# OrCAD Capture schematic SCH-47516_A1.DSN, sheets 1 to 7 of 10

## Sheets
1 TITLE, TOC & REV: title: LPC55S06-EVK; rev: A1; company: NXP Semiconductors; note: SCH-47516 PDF: SPF-47516; note: 6501 William Cannon Drive West; note: Austin, TX 78735-8598
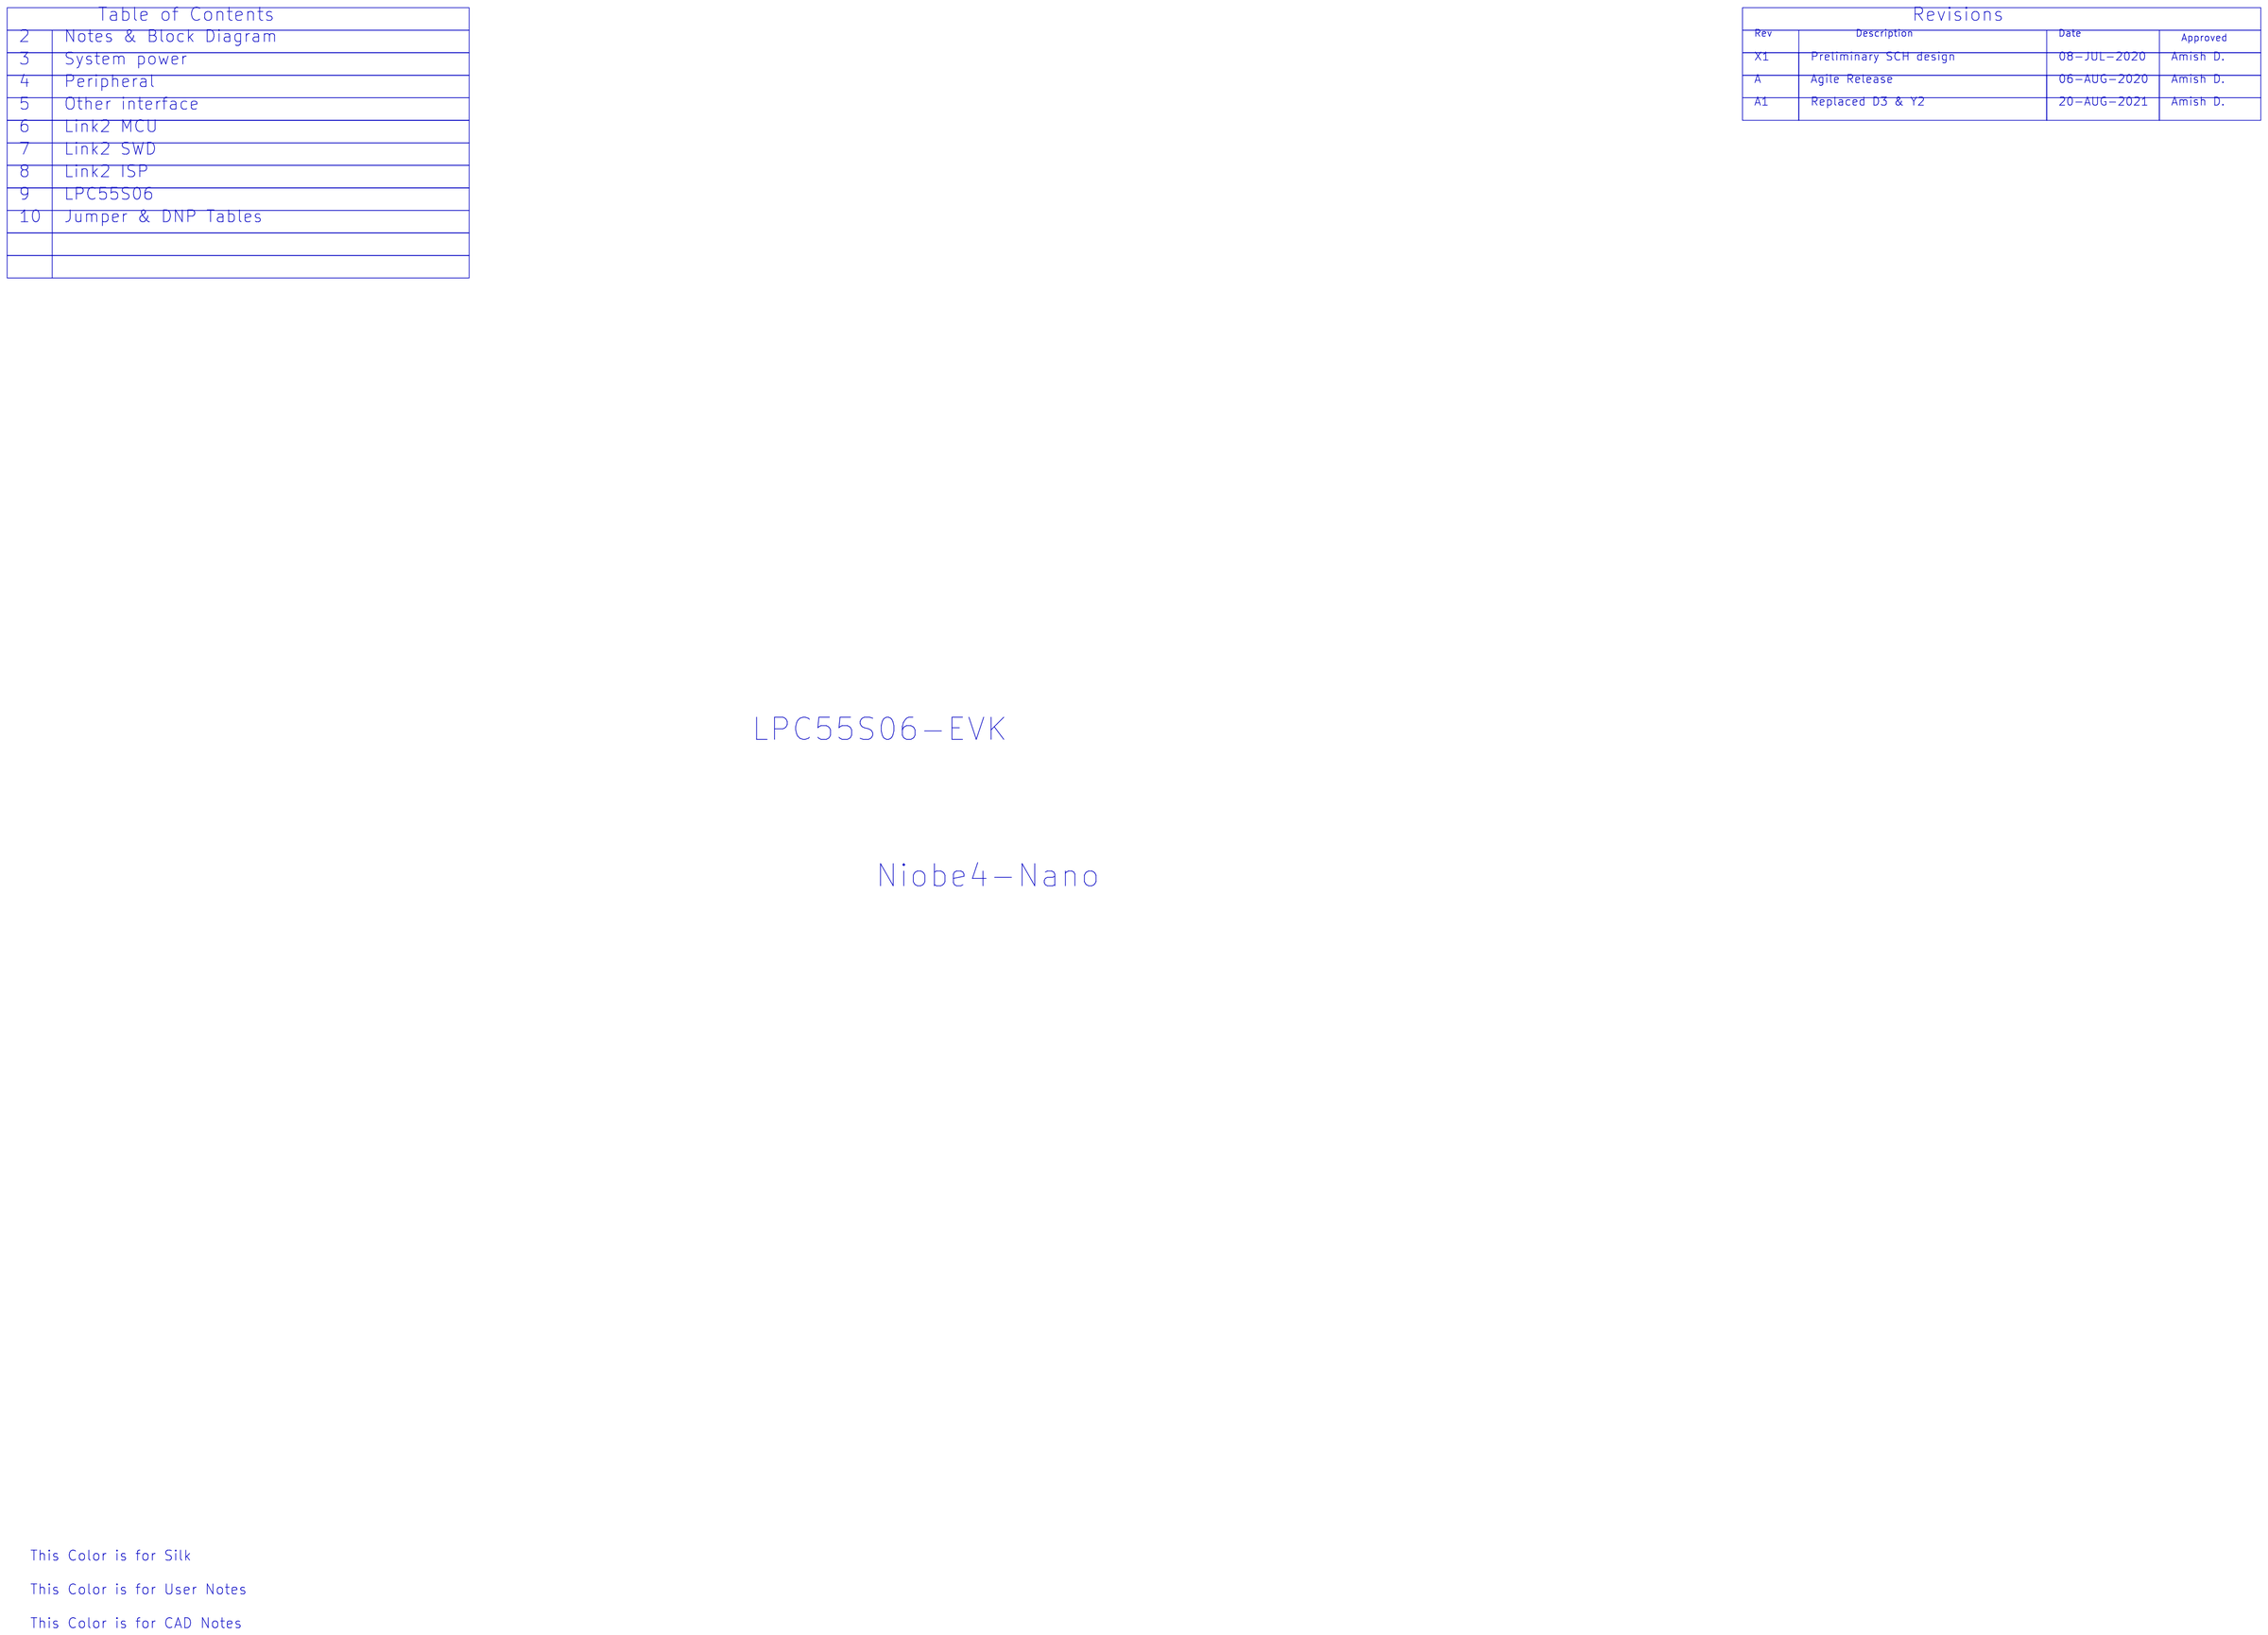
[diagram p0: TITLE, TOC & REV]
2 Block Diagram
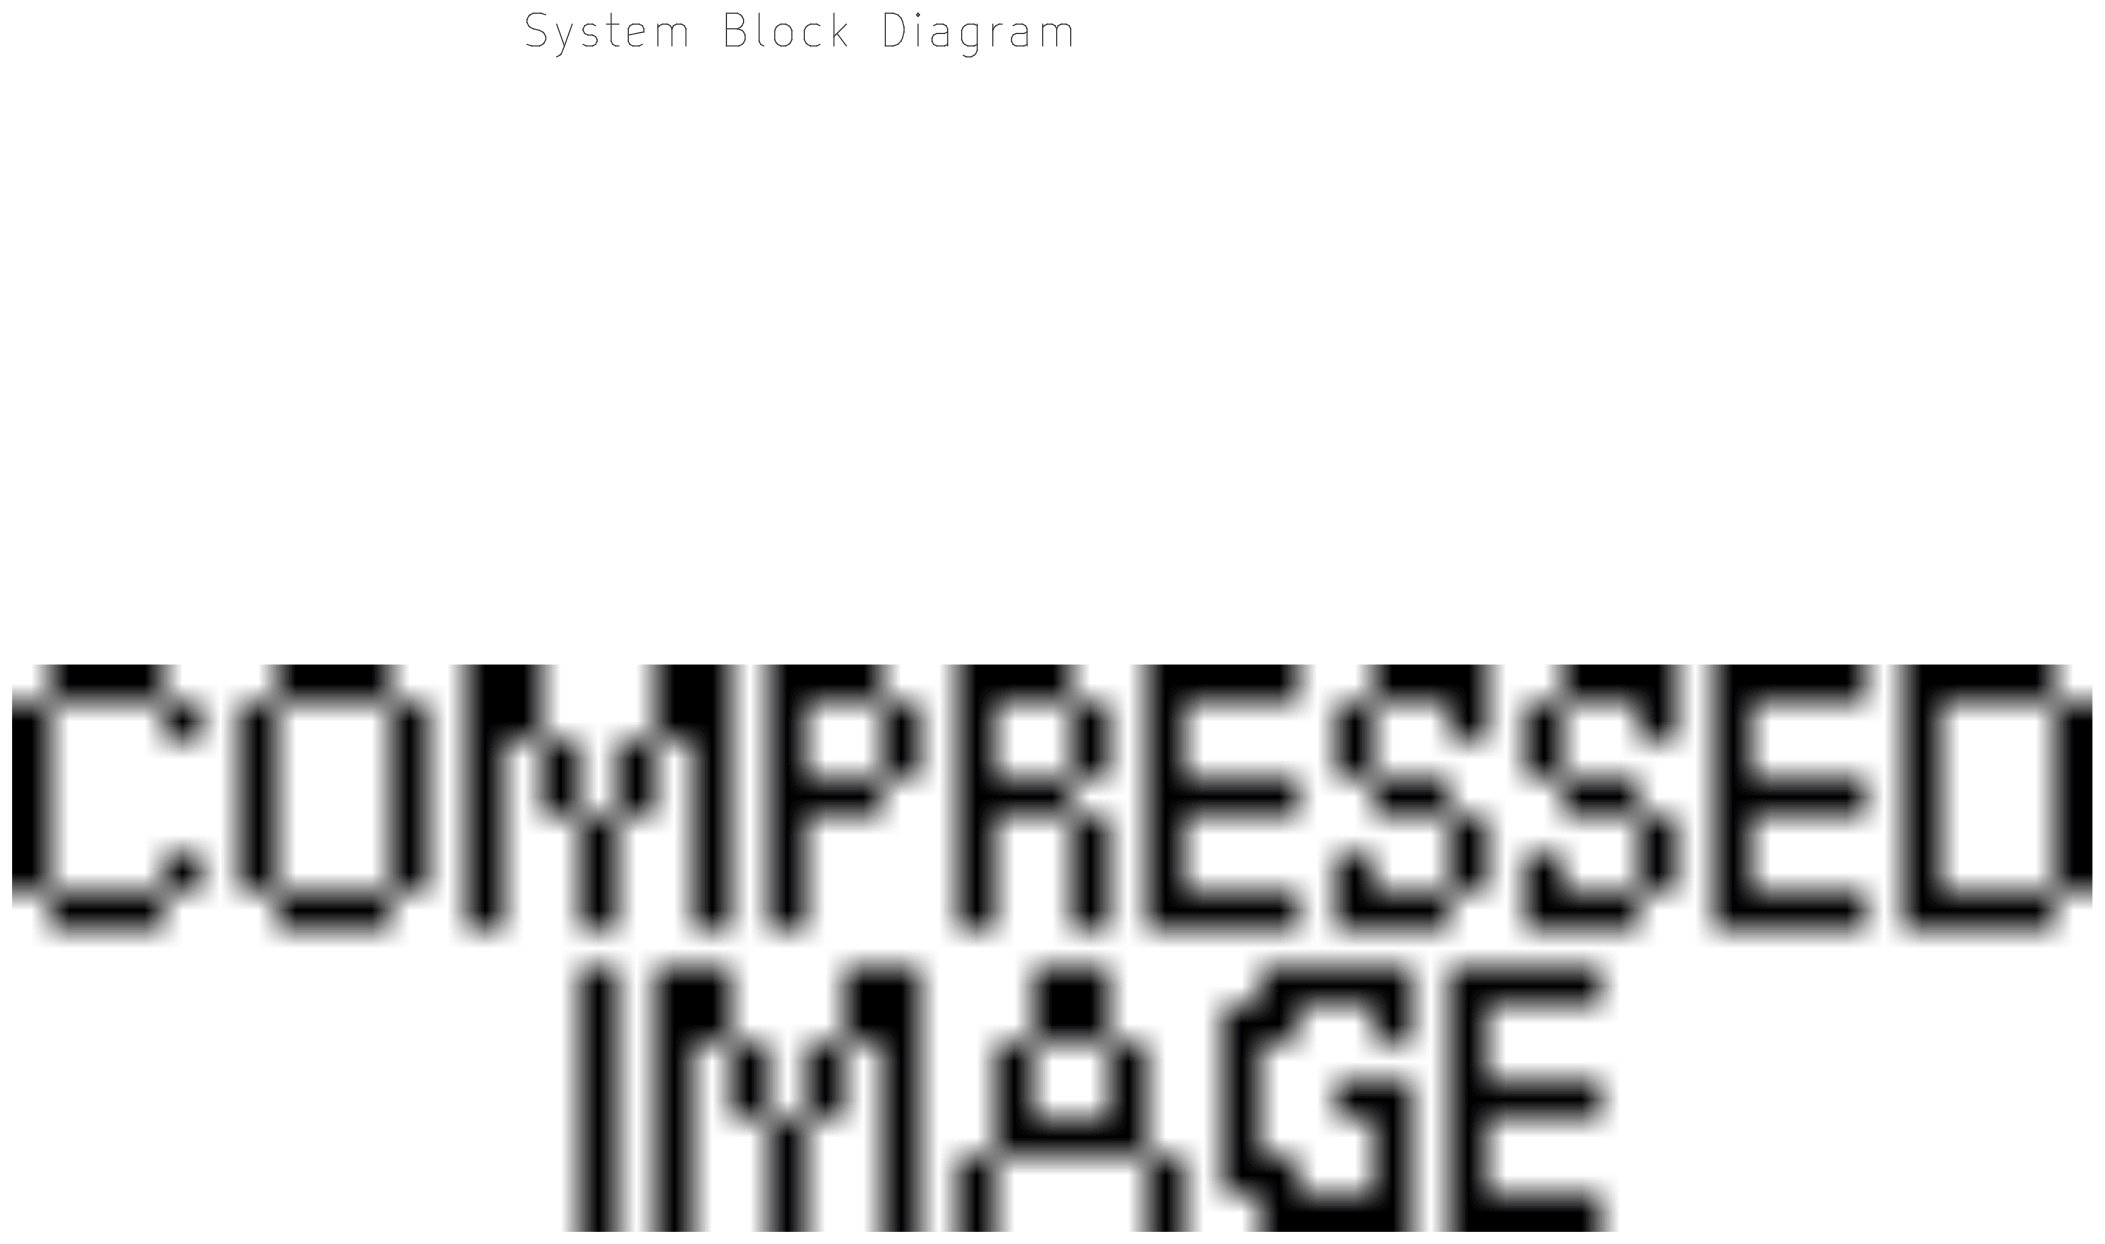
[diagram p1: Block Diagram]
3 System Power: size C
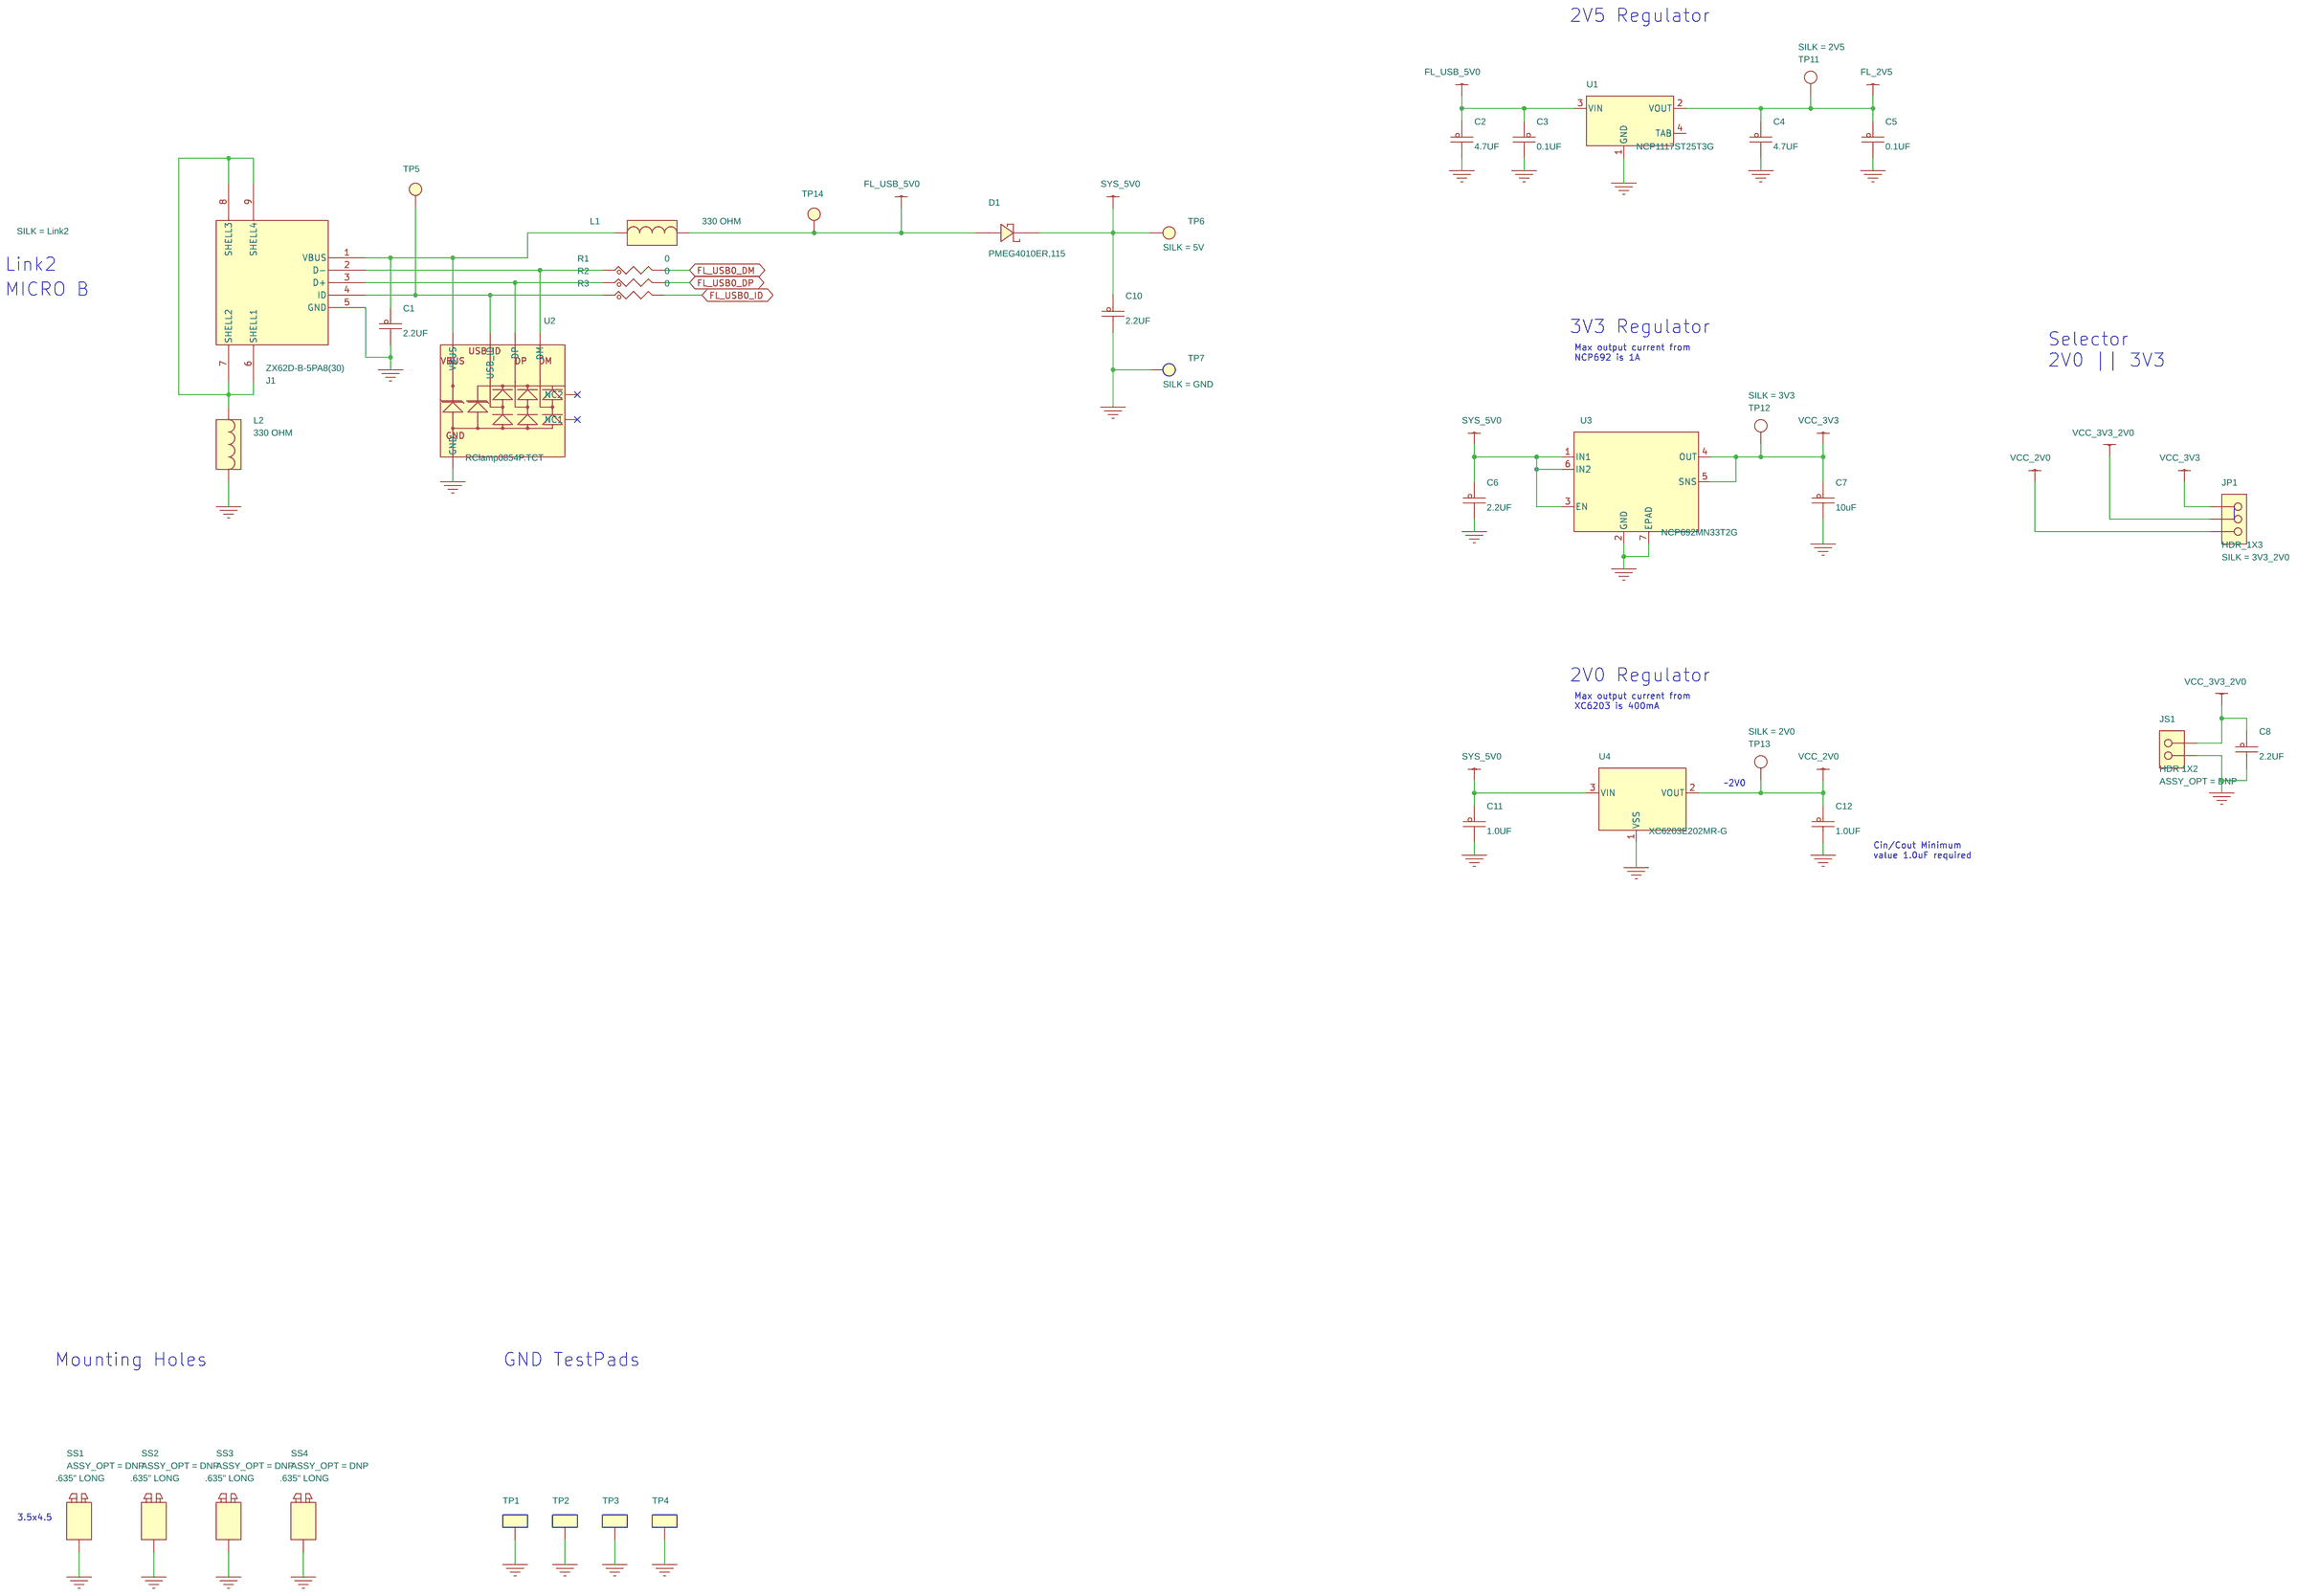
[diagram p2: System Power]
4 Peripheral: size C
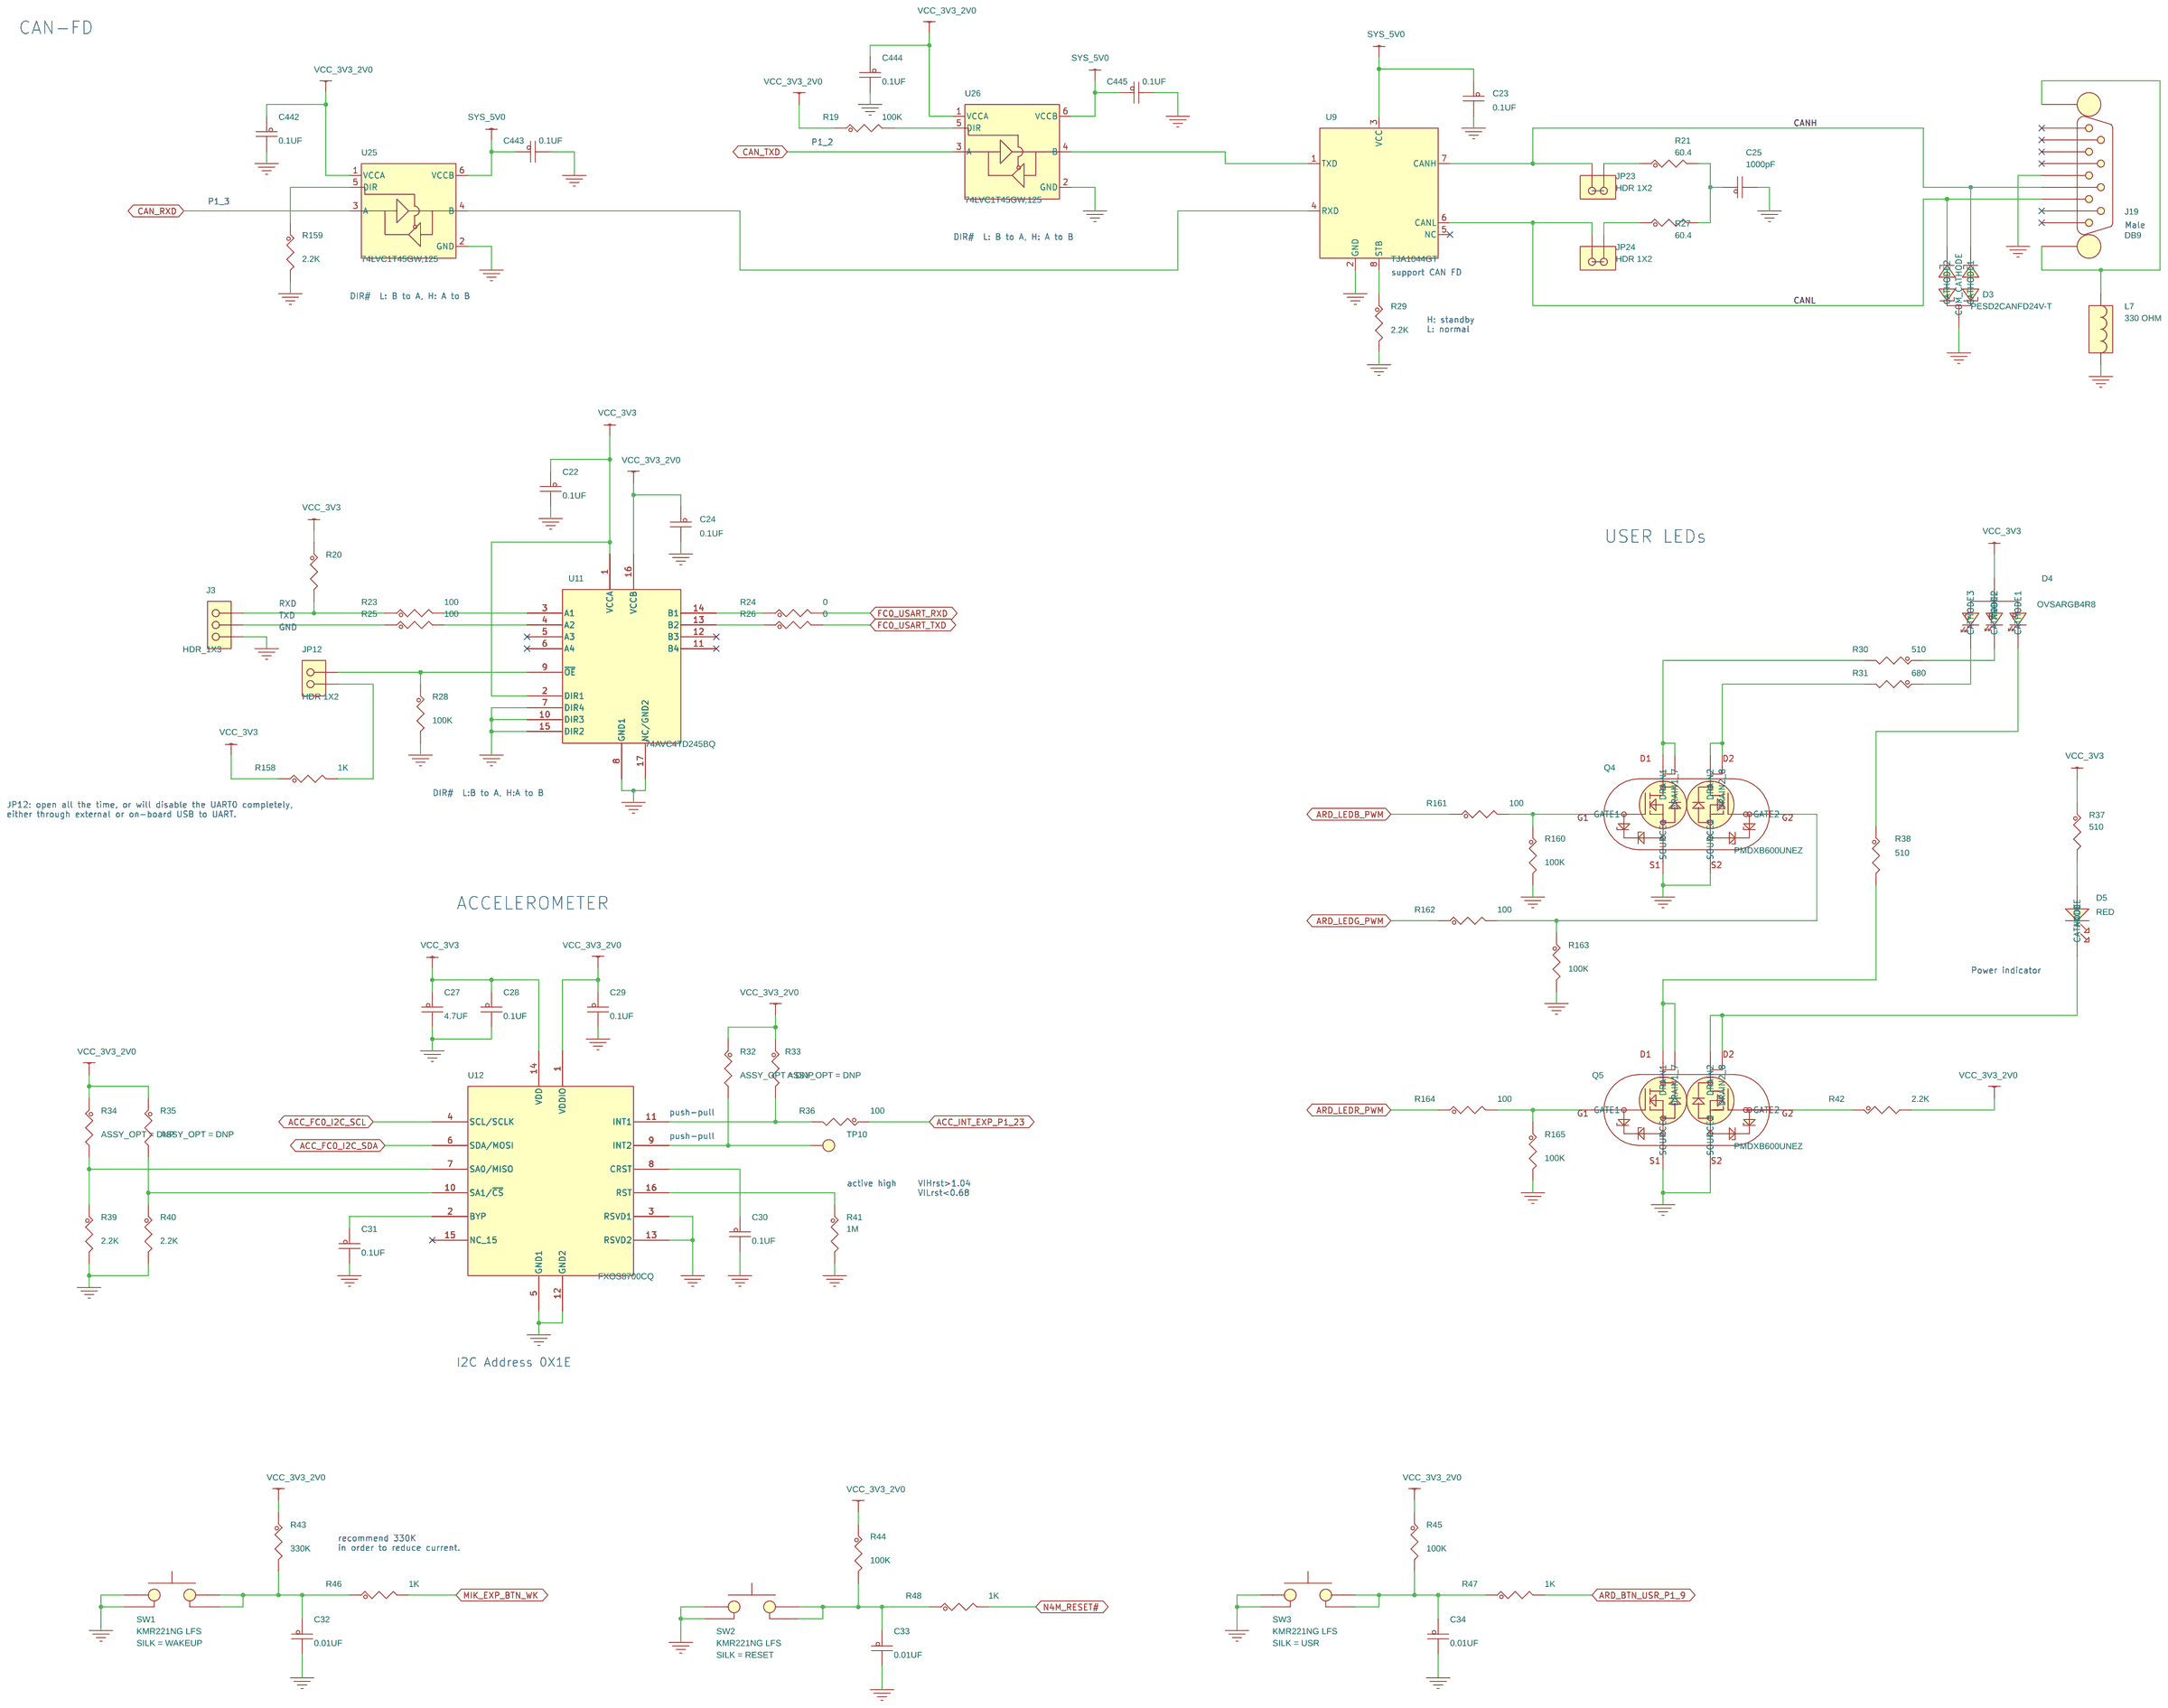
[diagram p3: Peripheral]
5 Other Interface: size C
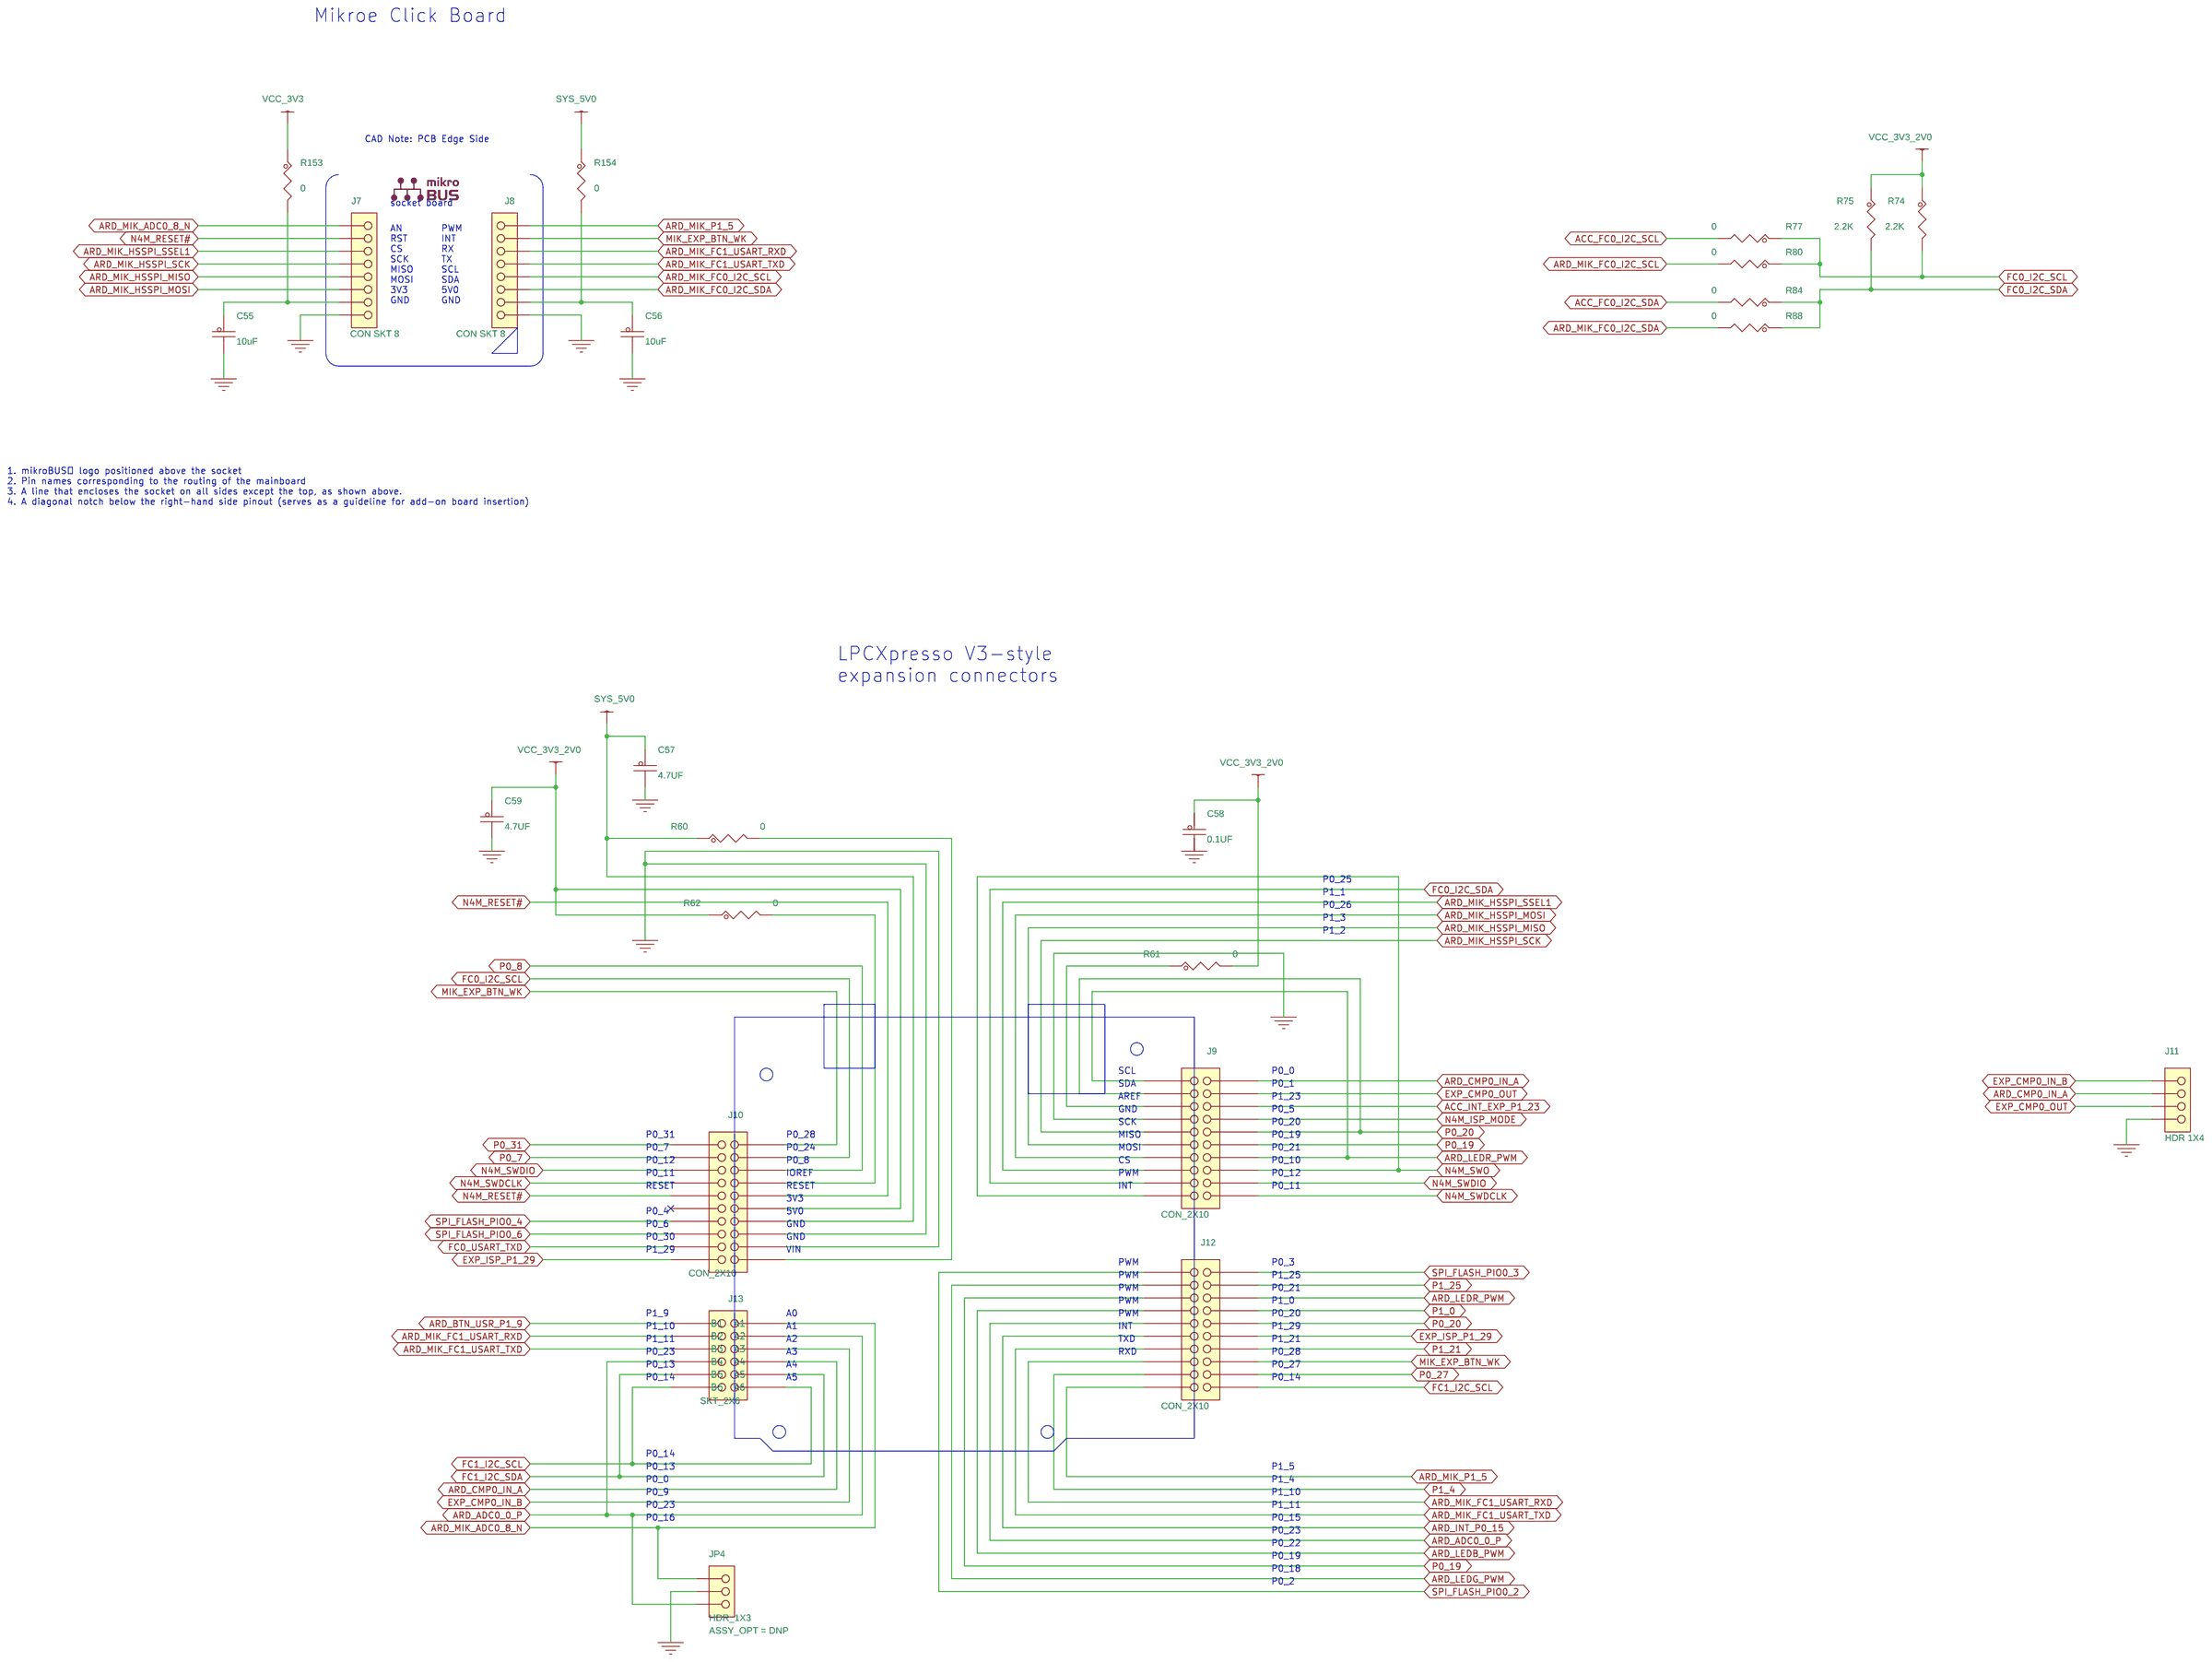
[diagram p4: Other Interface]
6 Link2 MCU: size C
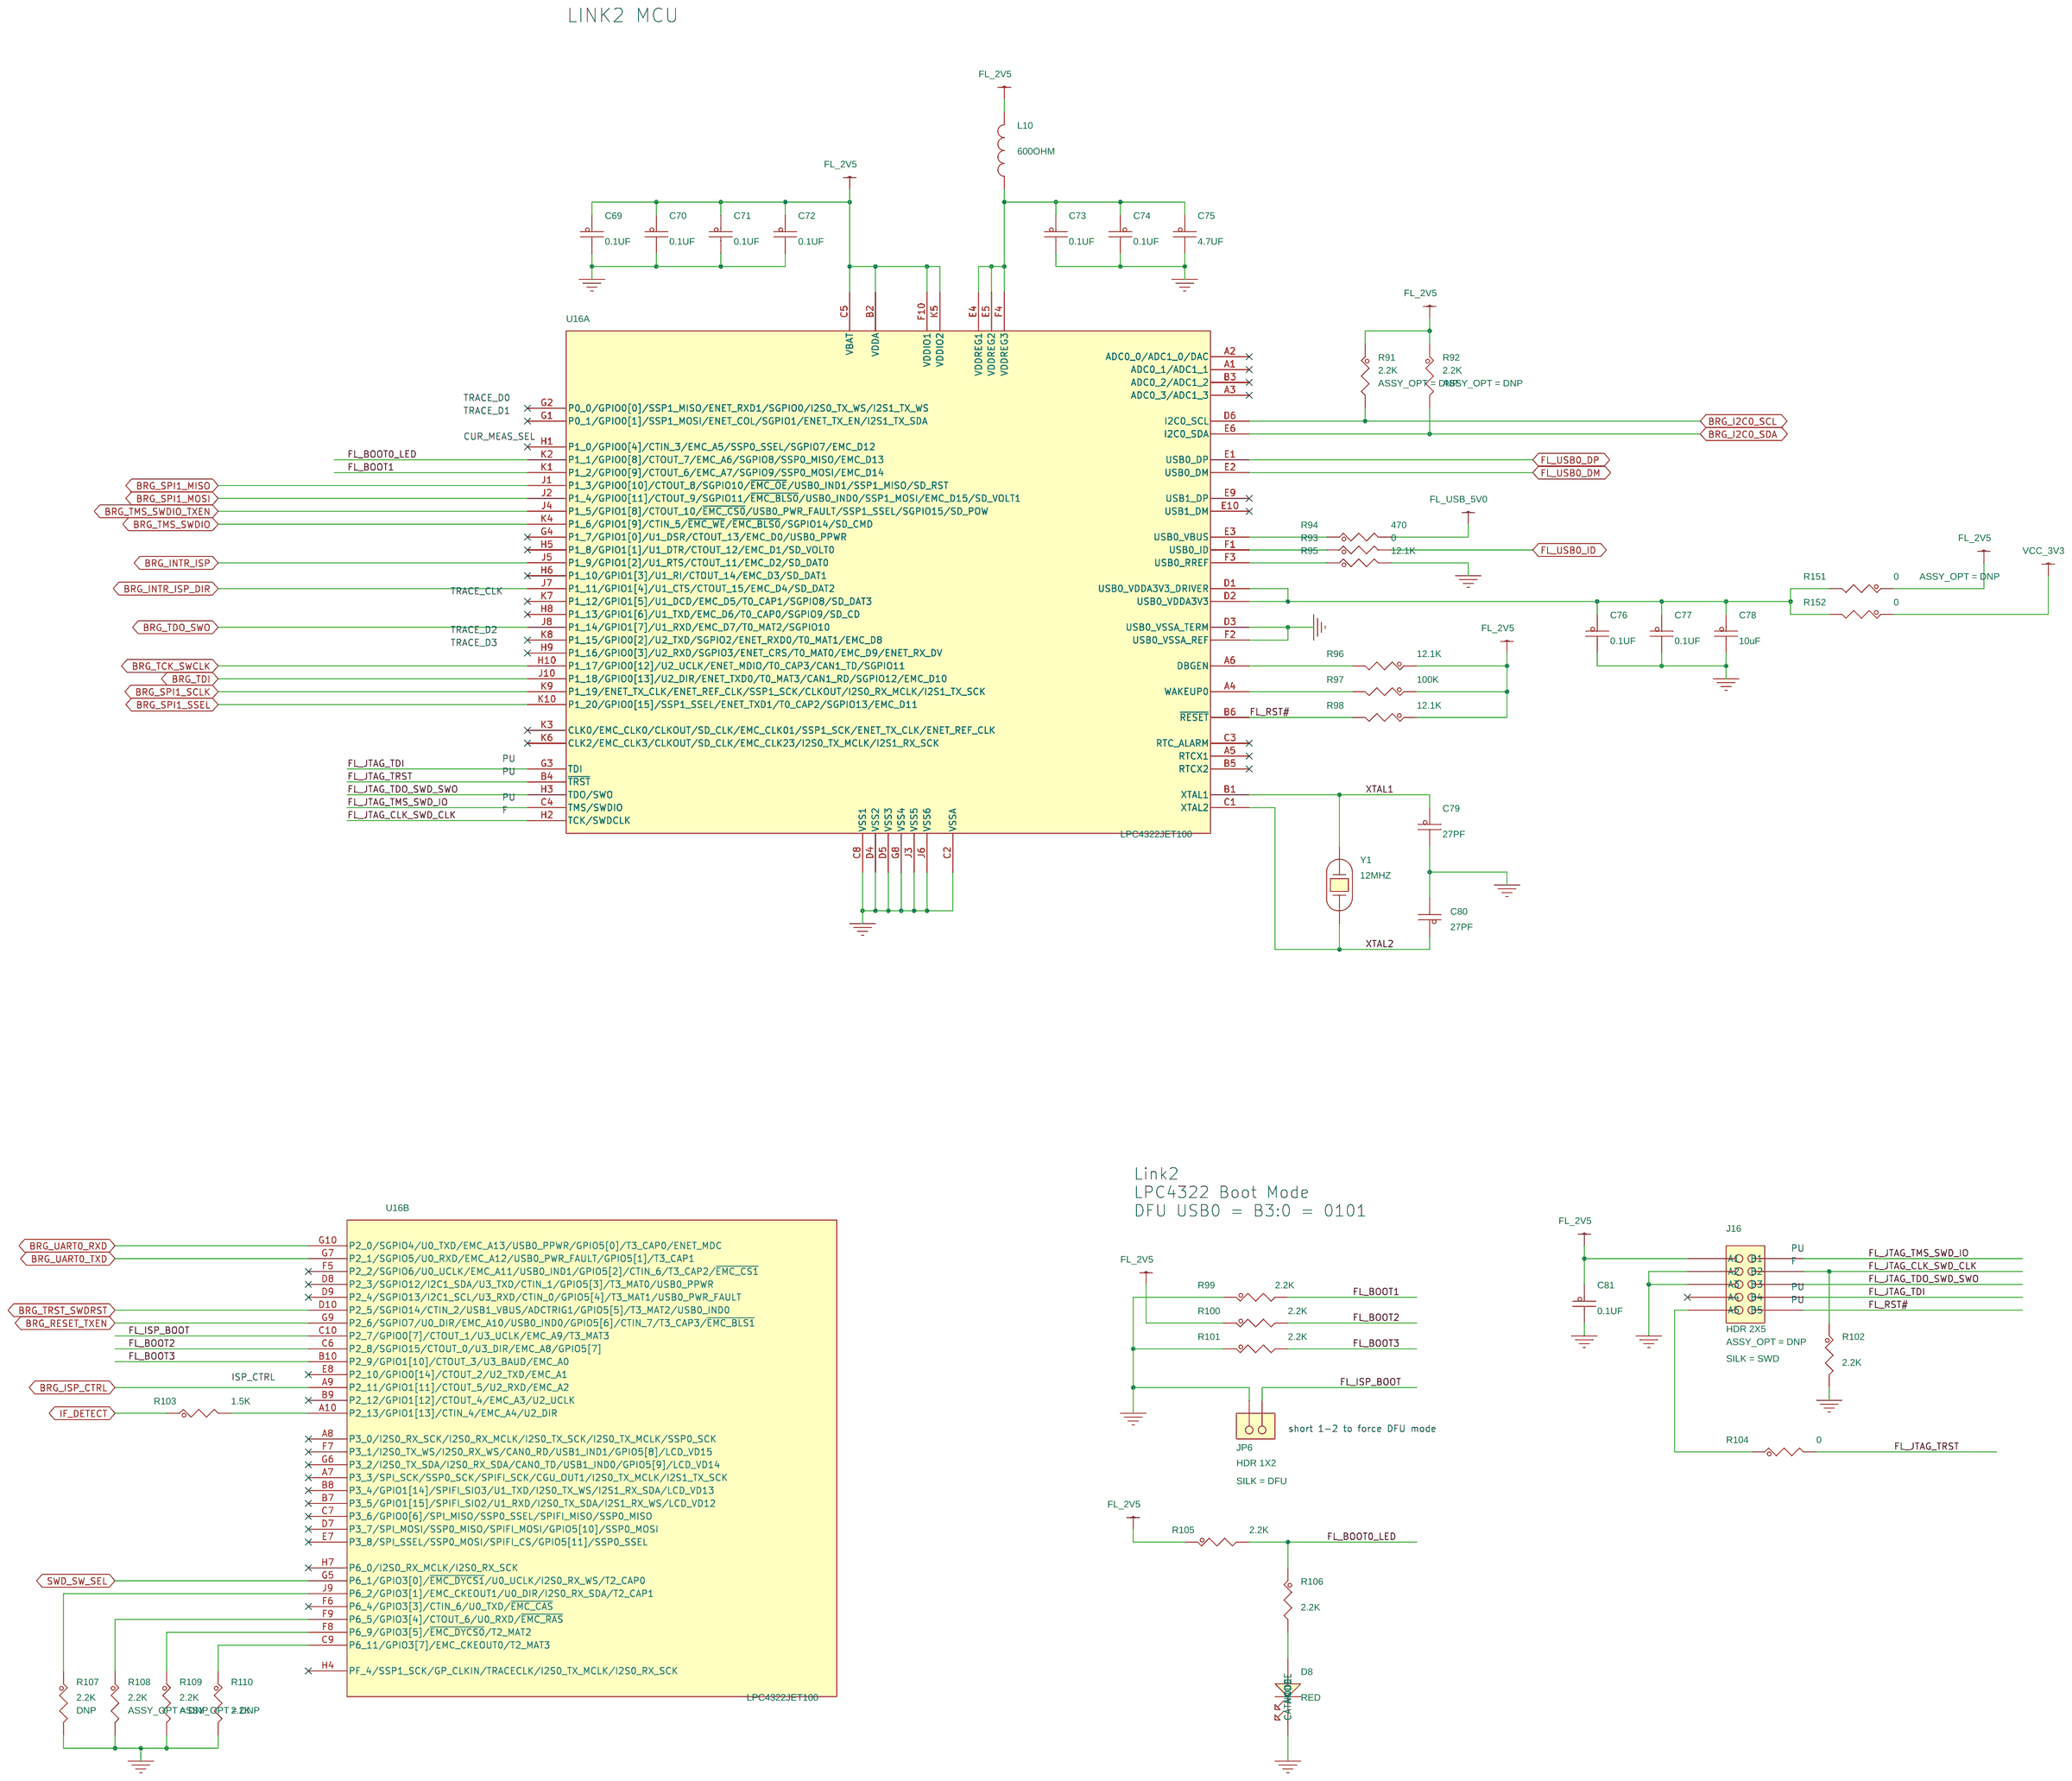
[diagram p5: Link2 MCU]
7 Link2 SWD: size C
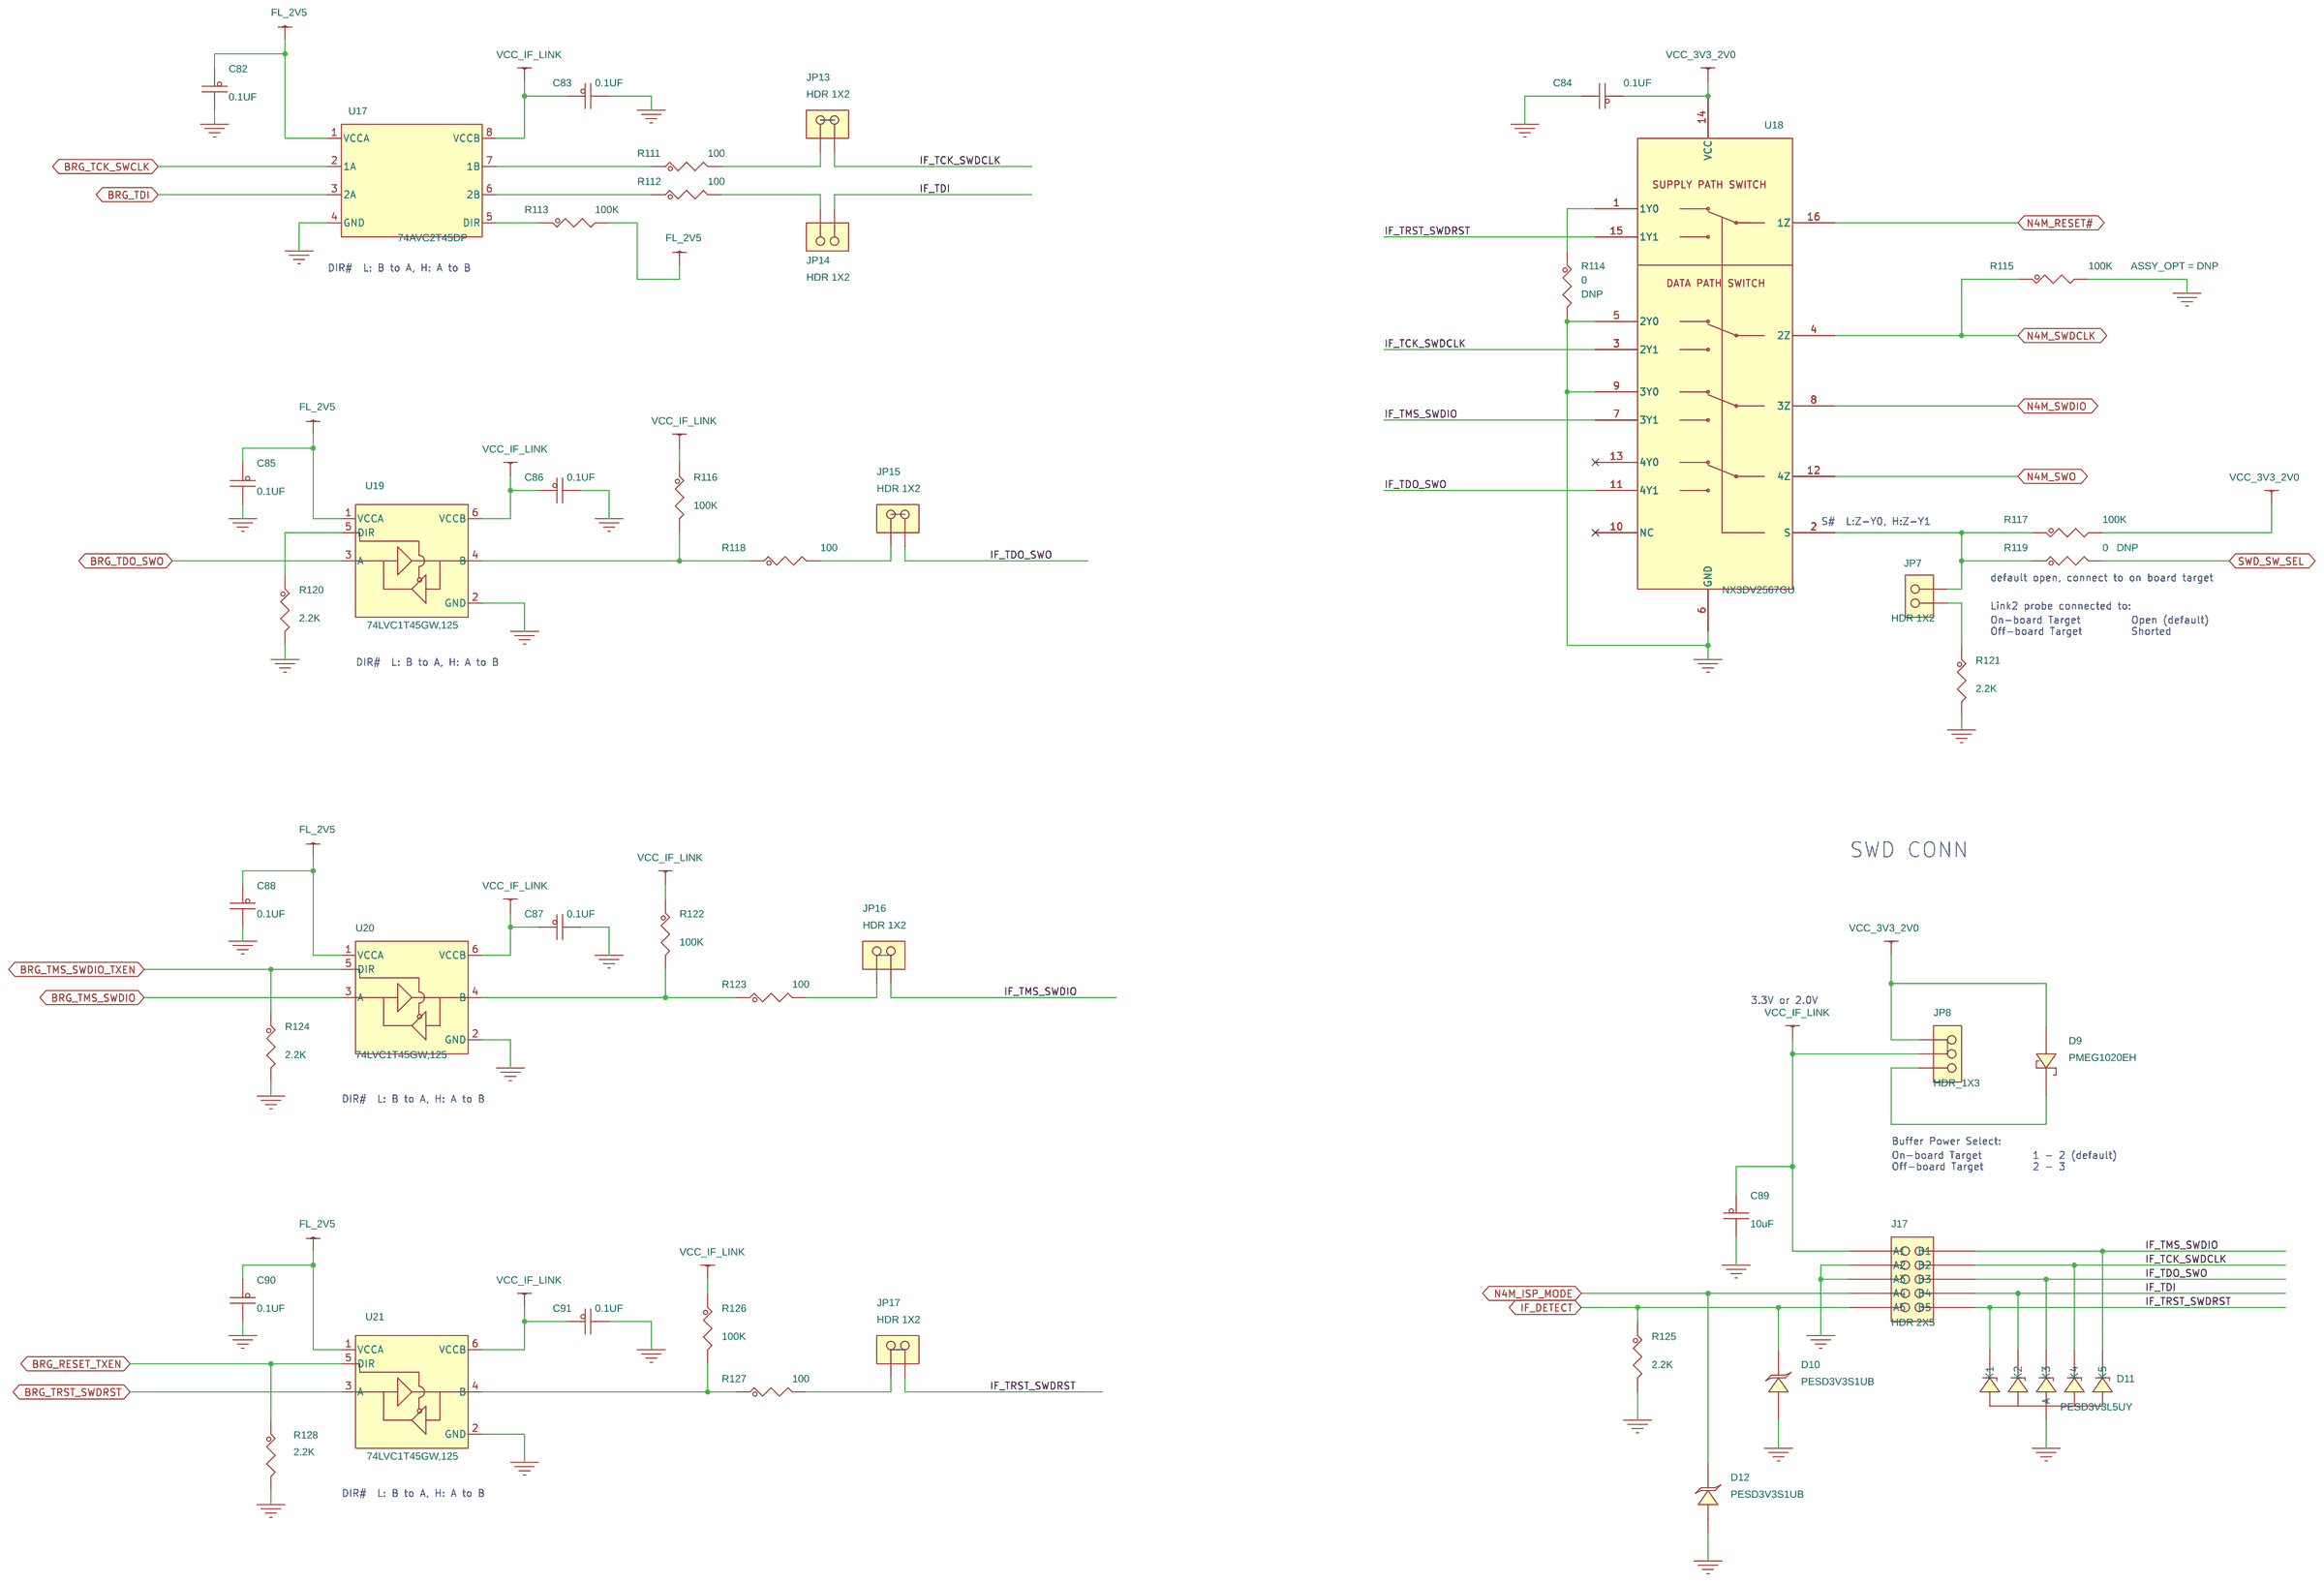
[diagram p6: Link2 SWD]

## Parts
sheet Link2 MCU
C69  0.1UF  [CC0402_25]
C70  0.1UF  [CC0402_25]
C71  0.1UF  [CC0402_25]
C72  0.1UF  [CC0402_25]
C73  0.1UF  [CC0402_25]
C74  0.1UF  [CC0402_25]
C75  4.7UF  [cc0402_tol0p15]
C76  0.1UF  [CC0402_25]
C77  0.1UF  [CC0402_25]
C78  10uF  [cc0402_tol0p2]
C79  27PF  [CC0402_25]
C80  27PF  [CC0402_25]
C81  0.1UF  [CC0402_25]
D8  RED  [LED_0603]
J16  HDR 2X5  [hdr205_50_th]
JP6  HDR 1X2  [HDR102]
L10  600OHM  [ind_1p8x1mm_sm]
R91  2.2K  [RC0402_25]
R92  2.2K  [RC0402_25]
R93  0  [RC0402_25]
R94  470  [RC0402_25]
R95  12.1K  [RC0402_25]
R96  12.1K  [RC0402_25]
R97  100K  [RC0402_25]
R98  12.1K  [RC0402_25]
R99  2.2K  [RC0402_25]
R100  2.2K  [RC0402_25]
R101  2.2K  [RC0402_25]
R102  2.2K  [RC0402_25]
R103  1.5K  [RC0402_25]
R104  0  [RC0402_25]
R105  2.2K  [RC0402_25]
R106  2.2K  [RC0402_25]
R107  2.2K  [RC0402_25]
R108  2.2K  [RC0402_25]
R109  2.2K  [RC0402_25]
R110  2.2K  [RC0402_25]
R151  0  [RC0402_25]
R152  0  [RC0402_25]
U16  LPC4322JET100  [fbga100_0p8_9x9]  (sections A,B)
Y1  12MHZ  [xtl2_11p6x4p85_sm]
sheet Link2 SWD
C82  0.1UF  [CC0402_25]
C83  0.1UF  [CC0402_25]
C84  0.1UF  [CC0402_25]
C85  0.1UF  [CC0402_25]
C86  0.1UF  [CC0402_25]
C87  0.1UF  [CC0402_25]
C88  0.1UF  [CC0402_25]
C89  10uF  [cc0402_tol0p2]
C90  0.1UF  [CC0402_25]
C91  0.1UF  [CC0402_25]
D9  PMEG1020EH  [SOD123LF]
D10  PESD3V3S1UB  [sod523]
D11  PESD3V3L5UY  [sot-363_0p65_smt]
D12  PESD3V3S1UB  [sod523]
J17  HDR 2X5  [hdr205_50_th]
JP7  HDR 1X2  [HDR102]
JP8  HDR_1X3  [HDR103]
JP13  HDR 1X2  [HDR102]
JP14  HDR 1X2  [HDR102]
JP15  HDR 1X2  [HDR102]
JP16  HDR 1X2  [HDR102]
JP17  HDR 1X2  [HDR102]
R111  100  [RC0402_25]
R112  100  [RC0402_25]
R113  100K  [RC0402_25]
R114  0  [RC0402_25]
R115  100K  [RC0402_25]
R116  100K  [RC0402_25]
R117  100K  [RC0402_25]
R118  100  [RC0402_25]
R119  0  [RC0402_25]
R120  2.2K  [RC0402_25]
R121  2.2K  [RC0402_25]
R122  100K  [RC0402_25]
R123  100  [RC0402_25]
R124  2.2K  [RC0402_25]
R125  2.2K  [RC0402_25]
R126  100K  [RC0402_25]
R127  100  [RC0402_25]
R128  2.2K  [RC0402_25]
U17  74AVC2T45DP  [msop_8p_0p65_3x3mm]
U18  NX3DV2567GU  [pqfn16_0p4_2p65x1p85]
U19  74LVC1T45GW,125  [SOT-363_0P65_SMT]
U20  74LVC1T45GW,125  [SOT-363_0P65_SMT]
U21  74LVC1T45GW,125  [SOT-363_0P65_SMT]
sheet Other Interface
C55  10uF  [cc0402_tol0p2]
C56  10uF  [cc0402_tol0p2]
C57  4.7UF  [cc0402_tol0p15]
C58  0.1UF  [CC0402_25]
C59  4.7UF  [cc0402_tol0p15]
J7  CON SKT 8  [con_1x8_skt_2p54_th]
J8  CON SKT 8  [con_1x8_skt_2p54_th]
J9  CON_2X10  [con_skt2x10_th]
J10  CON_2X10  [con_skt2x10_th]
J11  HDR 1X4  [hdr1x4_2p54_th]
J12  CON_2X10  [con_skt2x10_th]
J13  SKT_2X6  [con_2x6_skt_100_th]
JP4  HDR_1X3  [HDR103]
R60  0  [RC0402_25]
R61  0  [RC0402_25]
R62  0  [RC0402_25]
R74  2.2K  [RC0402_25]
R75  2.2K  [RC0402_25]
R77  0  [RC0402_25]
R80  0  [RC0402_25]
R84  0  [RC0402_25]
R88  0  [RC0402_25]
R153  0  [RC0402_25]
R154  0  [RC0402_25]
sheet Peripheral
C22  0.1UF  [CC0402_25]
C23  0.1UF  [CC0402_25]
C24  0.1UF  [CC0402_25]
C25  1000pF  [CC0402_25]
C27  4.7UF  [cc0402_tol0p15]
C28  0.1UF  [CC0402_25]
C29  0.1UF  [CC0402_25]
C30  0.1UF  [CC0402_25]
C31  0.1UF  [CC0402_25]
C32  0.01UF  [CC0402_25]
C33  0.01UF  [CC0402_25]
C34  0.01UF  [CC0402_25]
C442  0.1UF  [CC0402_25]
C443  0.1UF  [CC0402_25]
C444  0.1UF  [CC0402_25]
C445  0.1UF  [CC0402_25]
D3  PESD2CANFD24V-T  [sot23_a]
D4  OVSARGB4R8  [led4_0p4_3p4x3mm]
D5  RED  [LED_0603]
J3  HDR_1X3  [HDR103]
J19  DB9  [con_db9s_th_ra_318]
JP12  HDR 1X2  [HDR102]
JP23  HDR 1X2  [HDR102]
JP24  HDR 1X2  [HDR102]
L7  330 OHM  [ind_1608]
Q4  PMDXB600UNEZ  [dfn1010n-6_0p35_1p15x1p05]
Q5  PMDXB600UNEZ  [dfn1010n-6_0p35_1p15x1p05]
R19  100K  [RC0402_25]
R20  10K  [0402_CC]
R21  60.4  [RC0603_OV]
R23  100  [RC0402_25]
R24  0  [RC0402_25]
R25  100  [RC0402_25]
R26  0  [RC0402_25]
R27  60.4  [RC0603_OV]
R28  100K  [RC0402_25]
R29  2.2K  [RC0402_25]
R30  510  [RC0402_25]
R31  680  [RC0402_25]
R32  10K  [0402_CC]
R33  10K  [0402_CC]
R34  10K  [0402_CC]
R35  10K  [0402_CC]
R36  100  [RC0402_25]
R37  510  [RC0402_25]
R38  510  [RC0402_25]
R39  2.2K  [RC0402_25]
R40  2.2K  [RC0402_25]
R41  1M  [RC0402_25]
R42  2.2K  [RC0402_25]
R43  330K  [RC0402_25]
R44  100K  [RC0402_25]
R45  100K  [RC0402_25]
R46  1K  [RC0402_25]
R47  1K  [RC0402_25]
R48  1K  [RC0402_25]
R158  1K  [RC0402_25]
R159  2.2K  [RC0402_25]
R160  100K  [RC0402_25]
R161  100  [RC0402_25]
R162  100  [RC0402_25]
R163  100K  [RC0402_25]
R164  100  [RC0402_25]
R165  100K  [RC0402_25]
SW1  KMR221NG LFS  [sw4_4p2x2p8_sm]
SW2  KMR221NG LFS  [sw4_4p2x2p8_sm]
SW3  KMR221NG LFS  [sw4_4p2x2p8_sm]
TP10  TPAD_050  [TPAD_050]
U9  TJA1044GT  [SO8_1P27_4X5]
U11  74AVC4TD245BQ  [dhvqfn16_0p5_3p6x2p6]
U12  FXOS8700CQ  [QFN5X3_0P5_3X3]
U25  74LVC1T45GW,125  [SOT-363_0P65_SMT]
U26  74LVC1T45GW,125  [SOT-363_0P65_SMT]
sheet System Power
C1  2.2UF  [CC0402_25]
C2  4.7UF  [cc0402_tol0p15]
C3  0.1UF  [CC0402_25]
C4  4.7UF  [cc0402_tol0p15]
C5  0.1UF  [CC0402_25]
C6  2.2UF  [CC0402_25]
C7  10uF  [cc0402_tol0p2]
C8  2.2UF  [CC0402_25]
C10  2.2UF  [CC0402_25]
C11  1.0UF  [0402_CC]
C12  1.0UF  [0402_CC]
D1  PMEG4010ER,115  [SOD123W]
J1  ZX62D-B-5PA8(30)  [con9_microB_usb_shell_th]
JP1  HDR_1X3  [HDR103]
JS1  HDR 1X2  [HDR102]
L1  330 OHM  [ind_1608]
L2  330 OHM  [ind_1608]
R1  0  [RC0402_25]
R2  0  [RC0402_25]
R3  0  [RC0402_25]
SS1  .635" LONG  [spacer_139t]
SS2  .635" LONG  [spacer_139t]
SS3  .635" LONG  [spacer_139t]
SS4  .635" LONG  [spacer_139t]
TP1  TP_2P7X4P7  [tp_2p7x4p7mm]
TP2  TP_2P7X4P7  [tp_2p7x4p7mm]
TP3  TP_2P7X4P7  [tp_2p7x4p7mm]
TP4  TP_2P7X4P7  [tp_2p7x4p7mm]
TP5  TP_35MIL  [testpoint_35mil]
TP6  TP_35MIL  [testpoint_35mil]
TP7  TP_35MIL  [testpoint_35mil]
TP11  TPAD_020  [tpad_020]
TP12  TPAD_020  [tpad_020]
TP13  TPAD_020  [tpad_020]
TP14  TP_35MIL  [testpoint_35mil]
U1  NCP1117ST25T3G  [sot223]
U2  RClamp0854P.TCT  [slp1616p6]
U3  NCP692MN33T2G  [dfn6_0p95_3x3]
U4  XC6203E202MR-G  [SOT-23]

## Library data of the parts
C3 C5 C22-C24 C28-C31 C58 C69-C74 C76 C77 C82-C88 C90 C91 C442-C445 = CAP_NP: CAP CER 0.1UF 16V 10% X7R 0402; AGILE_PN: 150-75182; CAD_APPROVED: Yes; FPLIST: CC0402_25,CC0402_HD,0402_CC; HEIGHT: 0.635MM; MFG_NAME01: AVX; MFG_PN01: 0402YC104KAT2A; ROHS: Yes; Temp Range: -55°C to +125°C; Temp_Range: -55°C to +125°C; Tolerance: 10%; VOLTAGE: 16V
C2 C4 C27 C57 C59 C75 = CAP_NP: CAP CER 4.7uF 10V 20% X5R 0402_WIDE; AGILE_PN: 150-79667; CAD_APPROVED: Yes; FPLIST: CC0402_25,CC0402_HD,0402_CC; HEIGHT: 0.7 MM; MFG_NAME01: MURATA; MFG_PN01: GRM155R61A475MEAA; Package Size: 0402; ROHS: Yes; Temp Range: -55 to 85; Temp_Range: -55 to 85; Tolerance: 20%; VOLTAGE: 10V
C7 C55 C56 C78 C89 = CAP_NP: CAP CER 10uF 10V 20% X5R 0402_WIDE; AGILE_PN: 150-79255; CAD_APPROVED: Yes; FPLIST: CC0402_25,CC0402_HD,0402_CC; HEIGHT: 0.7MM; MFG_NAME01: NIC COMPONENTS CORP; MFG_PN01: NMC0402X5R106M10TRPF; ROHS: Yes; Tolerance: 20%; VOLTAGE: 10V
C79 C80 = CAP_NP: CAP CER 27PF 50V 5% C0G 0402; AGILE_PN: 150-30109; CAD_APPROVED: Yes; FPLIST: CC0402_25,CC0402_HD,0402_CC; HEIGHT: .55mm; MFG_NAME01: KEMET; MFG_PN01: C0402C270J5GAC; ROHS: Yes; Tolerance: 5%; VOLTAGE: 50V
C81 = CAP_NP: CAP CER 0.1UF 16V 10% X7R 0402; AGILE_PN: 150-75182; CAD_APPROVED: Yes; FPLIST: CC0402_25,CC0402_HD,0402_CC,CAPC0402_L; HEIGHT: 0.635MM; MFG_NAME01: AVX; MFG_PN01: 0402YC104KAT2A; ROHS: Yes; Temp Range: -55°C to +125°C; Temp_Range: -55°C to +125°C; Tolerance: 10%; VOLTAGE: 16V
D5 D8 = LED: LED RED SGL 20MA SMT; AGILE_PN: 370-76568; CAD_APPROVED: Yes; HEIGHT: 0.67MM; MFG_NAME01: OSRAM; MFG_PN01: LS L29K-H1J2-1; ROHS: Yes; VOLTAGE: 1.8V
J16 = CONN_HDR_5X2: HDR 2X5 TH 50MIL CTR 172H AU 91L; AGILE_PN: 210-81466; ASSY_OPT: DNP; CAD_APPROVED: Yes; HEIGHT: 4.38MM; MFG_NAME01: ANYTRONIC CORPORATION LIMITED; MFG_PN01: 0922S0205011N9T-31RF; ROHS: Yes; SILK: SWD; Temp Range: -55DegC to +105DegC; Temp_Range: -55DegC to +105DegC
JP6 = CONN_HDR_2X1: HDR 1X2 TH 100MIL SP 339H AU 98L; AGILE_PN: 210-81490; CAD_APPROVED: Yes; HEIGHT: 8.59MM; Jumper (Default): OPEN; MFG_NAME01: ANYTRONIC CORPORATION LIMITED; MFG_PN01: 0901S0202011N9T-31RF; ROHS: Yes; SILK: DFU; Temp Range: -55°C to +105°C; Temp_Range: -55°C to +105°C
L10 = INDUCTOR: IND FER BEAD 600OHM@100MHz 1A 25% 0603; AGILE_PN: 180-78469; CAD_APPROVED: Yes; HEIGHT: 1MM; MFG_NAME01: WURTH ELEKTRONIK EISOS GMBH & CO. KG (ELECTRONIC & ELECTROMEHANICAL COMP); MFG_PN01: 742792651; PART_TYPE: FERRITE\BEAD; ROHS: Yes; Tolerance: +/-25%
R91 R92 R107-R109 = RES: RES MF 2.2K 1/16W 1% 0402; AGILE_PN: 470-78359; ASSY_OPT: DNP; CAD_APPROVED: Yes; FPLIST: RC0402_25,RC0402_HD,0402_CC; HEIGHT: 0.4MM; MFG_NAME01: WALSIN TECHNOLOGY CORP.; MFG_PN01: WR04X2201FTL; ROHS: Yes; Temp Range: -55C to +155C; Temp_Range: -55C to +155C; Tolerance: 1%
R1-R3 R24 R26 R60-R62 R77 R80 R84 R88 R93 R104 R152-R154 = RES: RES MF ZERO OHM 1/16W -- AEC-Q200 0402; AGILE_PN: 470-81849; CAD_APPROVED: Yes; FPLIST: RC0402_25,RC0402_HD,0402_CC; HEIGHT: 0.45 MM; MFG_NAME01: STACKPOLE ELECTRONICS; MFG_PN01: RMCF0402ZT0R00; ROHS: Yes
R94 = RES: RES MF 470 OHM 1/16W 1% 0402; AGILE_PN: 470-76469; CAD_APPROVED: Yes; FPLIST: RC0402_25,RC0402_HD,0402_CC; HEIGHT: 0.4 MM; MFG_NAME01: THYE MING TECH CO LTD; MFG_PN01: CR-02FL6--470R; ROHS: Yes; Tolerance: 1%; VOLTAGE: 50V
R95 R96 R98 = RES: RES MF 12.1K 1/16W 1% 0402; AGILE_PN: 470-76098; CAD_APPROVED: Yes; FPLIST: RC0402_25,RC0402_HD,0402_CC; HEIGHT: 0.4 MM; MFG_NAME01: BOURNS; MFG_PN01: CR0402-FX-1212GLF; ROHS: Yes; Tolerance: 1%
R19 R28 R44 R45 R97 R113 R116 R117 R122 R126 R160 R163 R165 = RES: RES MF 100K 1/16W 1% 0402; AGILE_PN: 470-76240; CAD_APPROVED: Yes; FPLIST: RC0402_25,RC0402_HD,0402_CC; HEIGHT: 0.4MM; MFG_NAME01: NIC COMPONENTS CORP; MFG_PN01: NRCL04F1003TRF; ROHS: Yes; Tolerance: 1%
R29 R39 R40 R42 R74 R75 R99-R102 R105 R106 R110 R120 R121 R124 R125 R128 R159 = RES: RES MF 2.2K 1/16W 1% 0402; AGILE_PN: 470-78359; CAD_APPROVED: Yes; FPLIST: RC0402_25,RC0402_HD,0402_CC; HEIGHT: 0.4MM; MFG_NAME01: WALSIN TECHNOLOGY CORP.; MFG_PN01: WR04X2201FTL; ROHS: Yes; Temp Range: -55C to +155C; Temp_Range: -55C to +155C; Tolerance: 1%
R103 = RES: RES MF 1.5K 1/16W 5% 0402; AGILE_PN: 470-76303; CAD_APPROVED: Yes; FPLIST: RC0402_25,RC0402_HD,0402_CC; HEIGHT: 0.40 MM; MFG_NAME01: VISHAY INTERTECHNOLOGY; MFG_PN01: CRCW04021K50JNED; ROHS: Yes; Tolerance: 5%; VOLTAGE: 1/16W
R114 R119 R151 = RES: RES MF ZERO OHM 1/16W -- AEC-Q200 0402; AGILE_PN: 470-81849; ASSY_OPT: DNP; CAD_APPROVED: Yes; FPLIST: RC0402_25,RC0402_HD,0402_CC; HEIGHT: 0.45 MM; MFG_NAME01: STACKPOLE ELECTRONICS; MFG_PN01: RMCF0402ZT0R00; ROHS: Yes
U16 = LPC432_BGA_100P: IC MCU  CORTEX M4 CORE 512kB FLASH 2.4-3.6V BGA100; AGILE_PN: 344-02176; CAD_APPROVED: Yes; HEIGHT: 1.2MM; MFG_NAME01: NXP SEMICONDUCTORS; MFG_PN01: LPC4322JET100E; ROHS: Yes; VOLTAGE: 2.4-3.6V
Y1 = XTAL: XTAL 12MHZ RSN -- 18PF 30PPM SMT; AGILE_PN: 230-78082; CAD_APPROVED: Yes; HEIGHT: 3.3MM; MFG_NAME01: ABRACON CORP; MFG_PN01: ABLS2-12.000MHZ-D4Y-T; ROHS: Yes
D9 = DIODE_SCHTKY: DIODE SCH RECT 10V 2A SOD123F; AGILE_PN: 480-78720; CAD_APPROVED: Yes; HEIGHT: 1.2M; MFG_NAME01: NEXPERIA; MFG_PN01: PMEG1020EH,115; ROHS: Yes; VOLTAGE: 10V
D10 D12 = DIODE_TVS: DIODE TVS UNIDIR 3.3VWM 20VC SOD523; AGILE_PN: 480-79814; CAD_APPROVED: Yes; HEIGHT: 0.65MM; MFG_NAME01: NEXPERIA; MFG_PN01: PESD3V3S1UB,115; REQUESTED_COMPLETION_DATE: Not an expedite request; ROHS: Yes
D11 = DIODE_ARRAY_5CH: DIODE TVS UNIDIR 3.3VWM 12VC SOT363; AGILE_PN: 480-79841; CAD_APPROVED: Yes; HEIGHT: 1.1MM; MFG_NAME01: NEXPERIA; MFG_PN01: PESD3V3L5UY,115; REQUESTED_COMPLETION_DATE: Not an expedite request; ROHS: Yes; Temp Range: -65°C ~ 150°C; Temp_Range: -65°C ~ 150°C
J17 = CONN_HDR_5X2: HDR 2X5 TH 50MIL CTR 172H AU 91L; AGILE_PN: 210-81466; CAD_APPROVED: Yes; HEIGHT: 4.38MM; Jumper (Default): OPEN; MFG_NAME01: ANYTRONIC CORPORATION LIMITED; MFG_PN01: 0922S0205011N9T-31RF; ROHS: Yes; Temp Range: -55DegC to +105DegC; Temp_Range: -55DegC to +105DegC
JP7 JP12 JP14 = CONN_HDR_2X1: HDR 1X2 TH 100MIL SP 339H AU 98L; AGILE_PN: 210-81490; CAD_APPROVED: Yes; HEIGHT: 8.59MM; Jumper (Default): OPEN; MFG_NAME01: ANYTRONIC CORPORATION LIMITED; MFG_PN01: 0901S0202011N9T-31RF; ROHS: Yes; Temp Range: -55°C to +105°C; Temp_Range: -55°C to +105°C
JP8 = CONN_HDR_3X1: HDR 1X3 TH 100MIL SP 338H AU 98L; AGILE_PN: 210-81491; CAD_APPROVED: Yes; HEIGHT: 8.59MM; Jumper (Default): 1-2; MFG_NAME01: ANYTRONIC CORPORATION LIMITED; MFG_PN01: 0901S0203011N9T-31RF; ROHS: Yes; Temp Range: -55°C to +105°C; Temp_Range: -55°C to +105°C
JP13 JP15-JP17 JP23 JP24 = CONN_HDR_2X1: HDR 1X2 TH 100MIL SP 339H AU 98L; AGILE_PN: 210-81490; CAD_APPROVED: Yes; HEIGHT: 8.59MM; Jumper (Default): 1-2; MFG_NAME01: ANYTRONIC CORPORATION LIMITED; MFG_PN01: 0901S0202011N9T-31RF; ROHS: Yes; Temp Range: -55°C to +105°C; Temp_Range: -55°C to +105°C
R23 R25 R36 R111 R112 R118 R123 R127 R161 R162 R164 = RES: RES MF 100 OHM 1/16W 5% 0402; AGILE_PN: 470-75591; CAD_APPROVED: Yes; FPLIST: RC0402_25,RC0402_HD,RC0402_X2,0402_CC; HEIGHT: 0.45mm; MFG_NAME01: NIC COMPONENTS CORP; MFG_PN01: NRCL04J101TRF; ROHS: Yes; Tolerance: 5%
R115 = RES: RES MF 100K 1/16W 1% 0402; AGILE_PN: 470-76240; ASSY_OPT: DNP; CAD_APPROVED: Yes; FPLIST: RC0402_25,RC0402_HD,0402_CC; HEIGHT: 0.4MM; MFG_NAME01: NIC COMPONENTS CORP; MFG_PN01: NRCL04F1003TRF; ROHS: Yes; Tolerance: 1%
U17 = 74AVC2T45_8P: IC XCVR 0.8-3.6V/0.8-3.6V TSSOP8; AGILE_PN: 312-80487; CAD_APPROVED: Yes; HEIGHT: 1.1 MM; MFG_NAME01: NEXPERIA; MFG_PN01: 74AVC2T45DP,125; ROHS: Yes; VOLTAGE: 0.8-3.6V
U18 = NX3DV2567GU_XQFN_16P: IC LIN SW 4PDT 1.4-4.3V XQFN16; AGILE_PN: 315-80822; CAD_APPROVED: Yes; HEIGHT: 0.5 MM; MFG_NAME01: NXP SEMICONDUCTORS; MFG_PN01: NX3DV2567GU,115; ROHS: Yes; VOLTAGE: 1.4-4.3V
U19-U21 U25 U26 = 74LVCH1T45_6P: IC XCVR XLATING DUAL 3-STATE 1.2- 5.5V TSSOP6; AGILE_PN: 312-81277; CAD_APPROVED: Yes; HEIGHT: 1.1MM; MFG_NAME01: NEXPERIA; ROHS: Yes; VOLTAGE: 1.2- 5.5V
J7 J8 = CONN_HDR_8X1: CON 1X8 SKT SHRD TH 100MIL SP 335H AU 126L; AGILE_PN: 210-78679; CAD_APPROVED: Yes; HEIGHT: 8.75MM; MFG_NAME01: SULLINS ELECTRONICS CORP; MFG_PN01: PPPC081LFBN-RC; ROHS: Yes
J9 J10 J12 = CONN_HDR_10X2: CON 2X10 SKT TH 100MIL CTR 343H AU 122L; AGILE_PN: 210-79497; CAD_APPROVED: Yes; FPLIST: con_skt2x10_th,con_skt2x10_th_mirror_nsp; HEIGHT: 8.7MM; MFG_NAME01: WURTH ELEKTRONIK EISOS GMBH & CO. KG (ELECTRONIC & ELECTROMEHANICAL COMP); MFG_PN01: 61302021821; ROHS: Yes
J11 = CONN_HDR_4X1: HDR 1X4 TH 2.54MM SP 344H AU 118L; AGILE_PN: 210-81920; CAD_APPROVED: Yes; HEIGHT: 8.69MM; JUMPER (DEFAULT): OPEN; MFG_NAME01: WURTH ELEKTRONIK EISOS GMBH & CO. KG (ELECTRONIC & ELECTROMEHANICAL COMP); MFG_PN01: 61300411121; Package Type: TH; ROHS: Yes; Temp Range: -40°C ~ 125°C; Temp_Range: -40°C ~ 125°C; VOLTAGE: 250V
J13 = CONN_HDR_6X2: CON 2X6 SKT TH 2.54MM CTR 339H AU 122L; AGILE_PN: 210-81685; CAD_APPROVED: Yes; HEIGHT: 8.6MM; MFG_NAME01: WURTH ELEKTRONIK EISOS GMBH & CO. KG (ELECTRONIC & ELECTROMEHANICAL COMP); MFG_PN01: 61301221821; ROHS: Yes; Temp Range: -40C to 125C; Temp_Range: -40C to 125C
JP4 = CONN_HDR_3X1: HDR 1X3 TH 100MIL SP 338H AU 98L; AGILE_PN: 210-81491; ASSY_OPT: DNP; CAD_APPROVED: Yes; HEIGHT: 8.59MM; MFG_NAME01: ANYTRONIC CORPORATION LIMITED; MFG_PN01: 0901S0203011N9T-31RF; ROHS: Yes; Temp Range: -55°C to +105°C; Temp_Range: -55°C to +105°C
C25 = CAP_NP: CAP CER 1000pF 50V 10% X7R AEC-Q200 0402; AGILE_PN: 150-79040; CAD_APPROVED: Yes; FPLIST: CC0402_25,CC0402_HD,0402_CC; HEIGHT: 0.55MM; MFG_NAME01: MURATA; MFG_PN01: GCM155R71H102KA37D; Package Size: 0402; Package Type: Paper Tape; ROHS: Yes; Tolerance: 10%; VOLTAGE: 50V
C32-C34 = CAP_NP: CAP CER 0.01UF 16V 20% X7R 0402; AGILE_PN: 150-30082; CAD_APPROVED: Yes; FPLIST: CC0402_25,CC0402_HD,0402_CC; HEIGHT: 0.56MM; MFG_NAME01: AVX; MFG_PN01: 0402YC103MAT2A; Package Size: 0402; ROHS: Yes; Tolerance: 20%; VOLTAGE: 16V
D3 = ESD_DIODE_2LINE: DIODE BIDIR CAN BUS ESD PROTECTION 2.6A 24V AEC-Q101 SOT23; 3D_Mechanical_Footprint_File: ftp://fcl.am.freescale.net/ALLEGRO/step/sot23_a.STEP; AGILE_PN: TMP-CIP-5695; CAD_APPROVED: Yes; HEIGHT: 1.1MM; MFG_NAME01: Nexperia; MFG_PN01: PESD2CANFD24V-TR; PRE_APN: 480-80386; Package Size: TO-236-3, SC-59, SOT-23-3; Rated Voltage: 24V; Temp Range: -55°C to +175°C; VOLTAGE: 24V (Max)
D4 = LED_GPLY6900: LED RGB MULTI 20MA SMT; AGILE_PN: 370-76772; CAD_APPROVED: Yes; HEIGHT: 2.1MM; MFG_NAME01: TT ELECTRONICS PLC; REQUESTED_COMPLETION_DATE: need sch symbol ASAP; ROHS: Yes; Temp Range: -40C - 100C; Temp_Range: -40C - 100C
J3 = CONN_HDR_3X1: HDR 1X3 TH 100MIL SP 338H AU 98L; AGILE_PN: 210-81491; CAD_APPROVED: Yes; HEIGHT: 8.59MM; Jumper (Default): OPEN; MFG_NAME01: ANYTRONIC CORPORATION LIMITED; MFG_PN01: 0901S0203011N9T-31RF; ROHS: Yes; Temp Range: -55°C to +105°C; Temp_Range: -55°C to +105°C
J19 = CONN_DB9M_MTGTABS: CON 9 DB MALE 0.318 PLUG RA SHLD TH 109MIL SP 500H -- 145L; AGILE_PN: 210-82038; CAD_APPROVED: Yes; HEIGHT: 12.7MM; MFG_NAME01: REGAL ELECTRONICS; MFG_PN01: R4019-09BT; Package Type: TH; ROHS: Yes; Temp Range: -55C to +105C; Temp_Range: -55C to +105C; VOLTAGE: 300V
L1 L2 L7 = BEAD: IND FER BEAD 330OHM@100MHZ 1.7A 0603; AGILE_PN: 180-78156; CAD_APPROVED: Yes; FPLIST: ind_1608,0603_CC; HEIGHT: 0.95MM; MFG_NAME01: TDK; MFG_PN01: MPZ1608S331A; PART_TYPE: FERRITE\BEAD; ROHS: Yes; Tolerance: 25%
Q4 Q5 = NMOS_DUAL_PMDXB600UNE_8P: TRAN NMOS PWR SW 600mA 20V 620mOHM DFN1010B-6; AGILE_PN: 480-79619; CAD_APPROVED: Yes; HEIGHT: 0.4MM; MFG_NAME01: NEXPERIA; ROHS: Yes; VOLTAGE: 20V
R20 = RES: RES MF 10K 1/16W 5% 0402; AGILE_PN: 470-75557; CAD_APPROVED: Yes; FPLIST: RC0402_25,RC0402_HD,0402_CC; HEIGHT: 0.4 MM; MFG_NAME01: VISHAY INTERTECHNOLOGY; MFG_PN01: CRCW040210K0JNED; ROHS: Yes; TOL: 5%; Tolerance: 5%
R21 R27 = RES: RES MF 60.4 OHM 1/10W 1% AEC-Q200 0603; AGILE_PN: 470-81807; CAD_APPROVED: Yes; FPLIST: RC0603_OV,RC0603,0603_CC; HEIGHT: 0.55MM; MFG_NAME01: VISHAY INTERTECHNOLOGY; MFG_PN01: CRCW060360R4FKEA; ROHS: Yes; Temp Range: -55C to +155C
R30 R37 R38 = RES: RES 510 OHMS 1/16W 5% RC0402 ROHS; AGILE_PN: 470-76237; CAD_APPROVED: Yes; FPLIST: RC0402_25,RC0402_HD,0402_CC; HEIGHT: 0.4 MM; MFG_NAME01: YAGEO AMERICA; MFG_PN01: RC0402JR-07510RL; ROHS: Yes
R31 = RES: RES MF 680 OHM 1/16W 5% 0402; AGILE_PN: 470-77301; CAD_APPROVED: Yes; FPLIST: RC0402_25,RC0402_HD,0402_CC; HEIGHT: 0.4MM; MFG_NAME01: PANASONIC; MFG_PN01: ERJ-2GEJ681X; ROHS: Yes; Tolerance: 5%; VOLTAGE: 50V
R32-R35 = RES: RES MF 10K 1/16W 5% 0402; AGILE_PN: 470-75557; ASSY_OPT: DNP; CAD_APPROVED: Yes; FPLIST: RC0402_25,RC0402_HD,0402_CC; HEIGHT: 0.4 MM; MFG_NAME01: VISHAY INTERTECHNOLOGY; MFG_PN01: CRCW040210K0JNED; ROHS: Yes; Tolerance: 5%
R41 = RES: RES MF 1M 1/10W 5% AEC-Q200 0402; AGILE_PN: 470-79978; CAD_APPROVED: Yes; FPLIST: RC0402_25,RC0402_HD,0402_CC; HEIGHT: 0.4MM; MFG_NAME01: KOA SPEER; MFG_PN01: RK73B1ETTP105J; ROHS: Yes; Temp Range: -55&#8451; to 155&#8451;; Temp_Range: -55&#8451; to 155&#8451;; Tolerance: 5%; VOLTAGE: 50V
R43 = RES: RES MF 330K 1/10W 1% AEC-Q200 0402; AGILE_PN: 470-81808; CAD_APPROVED: Yes; FPLIST: RC0402_25,RC0402_HD,0402_CC; HEIGHT: 0.40 MM; MFG_NAME01: KOA SPEER; MFG_PN01: RK73H1ETTP3303F; ROHS: Yes; Temp Range: -55C to +155C; Temp_Range: -55C to +155C; Tolerance: 1%; VOLTAGE: 50V
R46-R48 R158 = RES: RES MF 1.0K 1/16W 5% 0402; AGILE_PN: 470-82125; CAD_APPROVED: Yes; FPLIST: RC0402_25,RC0402_HD,RC0402_X2,0402_CC; HEIGHT: 0.4MM; MFG_NAME01: NIC COMPONENTS CORP; MFG_PN01: NRCL04J102TRF; ROHS: Yes; Temp Range: -55°C to +155°C; Temp_Range: -55°C to +155°C; Tolerance: 5%
SW1 = SW_PB_4P: SW SPST MOM PB NO 50MA 32V SMT; AGILE_PN: 510-78172; CAD_APPROVED: Yes; HEIGHT: 1.9 MM; MFG_NAME01: C&K COMPONENTS; ROHS: Yes; SILK: WAKEUP; Temp Range: -40° C to +85° C; Temp_Range: -40° C to +85° C; VOLTAGE: 32V
SW2 = SW_PB_4P: SW SPST MOM PB NO 50MA 32V SMT; AGILE_PN: 510-78172; CAD_APPROVED: Yes; HEIGHT: 1.9 MM; MFG_NAME01: C&K COMPONENTS; ROHS: Yes; SILK: RESET; Temp Range: -40° C to +85° C; Temp_Range: -40° C to +85° C; VOLTAGE: 32V
SW3 = SW_PB_4P: SW SPST MOM PB NO 50MA 32V SMT; AGILE_PN: 510-78172; CAD_APPROVED: Yes; HEIGHT: 1.9 MM; MFG_NAME01: C&K COMPONENTS; ROHS: Yes; SILK: USR; Temp Range: -40° C to +85° C; Temp_Range: -40° C to +85° C; VOLTAGE: 32V
TP10 = TEST_POINT_L: TEST POINT PAD 50MIL DIA SMT, NO PART TO ORDER; AGILE_PN: 211-76644; CAD_APPROVED: Yes; EN: 666-1-00186; HEIGHT: 0.1MM; KEY Number: 666-1-00186@1; MFG_NAME01: NOTACOMPONENT; MFG_PN01: NOTACOMPONENT; Mfg: NA; Mfg Part No: 666-1-00186; ROHS: Yes
U9 = TJA1044GT: IC XCVR CAN HS 4.75-5.25V AEC-Q100 SO8; AGILE_PN: 312-81317; CAD_APPROVED: Yes; HEIGHT: 1.75 MM; MFG_NAME01: NXP SEMICONDUCTORS; MFG_PN01: TJA1044GTJ; ROHS: Yes; VOLTAGE: 4.75-5.25V
U11 = 74AVC4TD245BQ_DHVQFN16: IC DUAL SUPPLY XCVR XLTR 4BIT 0-3.6V DHVQFN16; 3D_Mechanical_Footprint_File: ftp://fcl.am.freescale.net/ALLEGRO/step/dhvqfn16_0p5_3p6x2p6.STEP; AGILE_PN: 312-81329; CAD_APPROVED: Yes; HEIGHT: 1MM; MFG_NAME01: NEXPERIA; MFG_PN01: 74AVC4TD245BQ,115; ROHS: Yes
U12 = FXOS8700CQ_QFN_16P: IC ACCELEROMETER AND MAGNETOMETER SENSOR 3-AXIS 2.5V QFN16; AGILE_PN: 312-80418; CAD_APPROVED: Yes; FPLIST: QFN5X3_0P5_3X3,QFN5X3_0P5_3X3_a; HEIGHT: 1.25MM; MFG_NAME01: FREESCALE SEMICONDUCTOR; ROHS: Yes; VOLTAGE: 2.5V
C1 C6 C8 C10 = CAP_NP: CAP CER 2.2UF 10V 10% X5R 0402; AGILE_PN: 150-79475; CAD_APPROVED: Yes; FPLIST: CC0402_25,CC0402_HD,0402_CC; HEIGHT: 0.56MM; MFG_NAME01: AVX; MFG_PN01: 0402ZD225KAT2A; Package Size: 0402; ROHS: Yes; Tolerance: 10%; VOLTAGE: 10V
C11 C12 = CAP_NP: CAP CER 1.0UF 10V 10% X5R 0402; AGILE_PN: 150-75772; CAD_APPROVED: Yes; FPLIST: CC0402_25,CC0402_HD,0402_CC; HEIGHT: 0.6MM; MFG_NAME01: YAGEO AMERICA; MFG_PN01: CC0402KRX5R6BB105; Package Size: 0402; ROHS: Yes; VOLTAGE: 10V; voltage rating: 10V
D1 = DIODE_SCHTKY: DIODE SCH RECT 40V 1A AEC-Q101 SOD123W; AGILE_PN: 480-79802; CAD_APPROVED: Yes; HEIGHT: 1.1MM; MFG_NAME01: NEXPERIA
J1 = MICRO_USB_CONN_9PIN: CON 5 MICRO USB_TYPE_B 2.0 RA SMT SKT TH 0.65MM SP 104H AU; AGILE_PN: 210-82071; CAD_APPROVED: Yes; HEIGHT: 2.65MM; MFG_NAME01: HIROSE; Package Type: TH; ROHS: Yes; SILK: Link2; Temp Range: -35 to 85&#8451;; Temp_Range: -35 to 85&#8451;; VOLTAGE: 100V
JP1 = CONN_HDR_3X1: HDR 1X3 TH 100MIL SP 338H AU 98L; AGILE_PN: 210-81491; CAD_APPROVED: Yes; HEIGHT: 8.59MM; Jumper (Default): 1-2; MFG_NAME01: ANYTRONIC CORPORATION LIMITED; MFG_PN01: 0901S0203011N9T-31RF; ROHS: Yes; SILK: 3V3_2V0; Temp Range: -55°C to +105°C; Temp_Range: -55°C to +105°C
JS1 = CONN_HDR_2X1: HDR 1X2 TH 100MIL SP 339H AU 98L; AGILE_PN: 210-81490; ASSY_OPT: DNP; CAD_APPROVED: Yes; HEIGHT: 8.59MM; MFG_NAME01: ANYTRONIC CORPORATION LIMITED; MFG_PN01: 0901S0202011N9T-31RF; ROHS: Yes; Temp Range: -55°C to +105°C; Temp_Range: -55°C to +105°C
SS1-SS4 = SPACER: FASTENER, STANDOFF 4.5MMX3.53XM3.0X0.5 ROUND THR .635"L BRASS; AGILE_PN: 280-76498; ASSY_OPT: DNP; CAD_APPROVED: Yes; HEIGHT: 16.13MM; MFG_NAME01: UNICORP; MFG_PN01: MSS251-R-1-A-16; ROHS: Yes
TP1-TP4 = TEST_POINT: TEST POINT RECT 2P7X4P7 MM NO PART TO ORDER; AGILE_PN: 510-78183; CAD_APPROVED: Yes; HEIGHT: 0.127MM; MFG_NAME01: NA; MFG_PN01: NO PART TO ORDER1; ROHS: Yes
TP5 = T_POINT_R: TEST POINT PAD .035 SMT, no part to order; AGILE_PN: 510-75618; CAD_APPROVED: Yes; HEIGHT: 0.1MM; ROHS: Yes
TP6 TP14 = T_POINT_R: TEST POINT PAD .035 SMT, no part to order; AGILE_PN: 510-75618; CAD_APPROVED: Yes; HEIGHT: 0.1MM; ROHS: Yes; SILK: 5V
TP7 = T_POINT_R: TEST POINT PAD .035 SMT, no part to order; AGILE_PN: 510-75618; CAD_APPROVED: Yes; HEIGHT: 0.1MM; ROHS: Yes; SILK: GND
TP11 = TestLoop: TEST POINT PAD 0.5MM DIA SMT, NO PART TO ORDER; AGILE_PN: 211-77484; CAD_APPROVED: Yes; HEIGHT: 0.1MM; ROHS: Yes; SILK: 2V5
TP12 = TestLoop: TEST POINT PAD 0.5MM DIA SMT, NO PART TO ORDER; AGILE_PN: 211-77484; CAD_APPROVED: Yes; HEIGHT: 0.1MM; ROHS: Yes; SILK: 3V3
TP13 = TestLoop: TEST POINT PAD 0.5MM DIA SMT, NO PART TO ORDER; AGILE_PN: 211-77484; CAD_APPROVED: Yes; HEIGHT: 0.1MM; ROHS: Yes; SILK: 2V0
U1 = LD1117AS18: IC VREG LDO 2.5V 1A 20V SOT-223; AGILE_PN: 315-80698; CAD_APPROVED: Yes; HEIGHT: 1.8MM; MFG_NAME01: ON Semiconductor; ROHS: Yes
U2 = RCLAMP1654P_NEW: DIODE TVS ARRAY 3 5.5V SLP1616P6; AGILE_PN: 480-78843; CAD_APPROVED: Yes; HEIGHT: 0.65MM; MFG_NAME01: SEMTECH CORP; ROHS: Yes; VOLTAGE: 5.5V
U3 = NCP692_6P: IC VREG LDO 3.3V 1A 6V DFN6; AGILE_PN: 315-79987; CAD_APPROVED: Yes; HEIGHT: 1MM; MFG_NAME01: ON SEMICONDUCTOR; ROHS: Yes; VOLTAGE: 6V
U4 = XC6203E202MR-G_SOT23_3: IC VREG 2V 400mA 8V SOT23-3; AGILE_PN: 315-82874; CAD_APPROVED: Yes; HEIGHT: 1.3 MM; MFG_NAME01: Torex Semiconductor Ltd; Package Size: TO-236-3, SC-59, SOT-23-3; ROHS: Yes; Supply Voltage: 8V max; Temp Range: -40  °C  85 °C; VOLTAGE: 2V

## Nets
GND: C1.2 C2.2 C3.2 C4.2 C5.2 C6.2 C7.2 C8.2 C10.2 C11.2 C12.2 C22.2 C23.2 C24.2 C25.2 C27.2 C28.2 C29.2 C30.2 C31.2 C32.2 C33.2 C34.2 C55.2 C56.2 C57.2 C58.2 C59.2 C69.2 C70.2 C71.2 C72.2 C73.2 C74.2 C75.2 C76.2 C77.2 C78.2 C79.2 C80.2 C81.2 C82.2 C83.2 C84.2 C85.2 C86.2 C87.2 C88.2 C89.2 C90.2 C91.2 C442.2 C443.2 C444.2 C445.2 D3.3(COM_CATHODE) D8.C(CATHODE) D10.A D11.2(A) D12.A J1.5(GND) J3.3 J7.8 J8.8 J9.8 J10.15 J10.17 J11.4 J16.3(A2) J16.5(A3) J17.3(A2) J17.5(A3) J19.3 JP4.2 JP6.2 JS1.2 L2.2 L7.2 Q4.1(SOURCE1) Q4.4(SOURCE2) Q5.1(SOURCE1) Q5.4(SOURCE2) R28.2 R29.2 R39.2 R40.2 R41.2 R95.2 R99.1 R101.1 R102.2 R107.2 R108.2 R109.2 R110.2 R114.2 R115.2 R120.2 R121.2 R124.2 R125.2 R128.2 R159.2 R160.2 R163.2 R165.2 SS1.1(NC) SS2.1(NC) SS3.1(NC) SS4.1(NC) SW1.3 SW1.4 SW2.3 SW2.4 SW3.3 SW3.4 TP1.1 TP2.1 TP3.1 TP4.1 TP7.1(TP) U1.1(GND) U2.7(GND) U3.2(GND) U3.7(EPAD) U4.1(VSS) U9.2(GND) U11.7(DIR4) U11.8(GND1) U11.10(DIR3) U11.15(DIR2) U11.17(NC/GND2) U12.3(RSVD1) U12.5(GND1) U12.12(GND2) U12.13(RSVD2) U16.C2(VSSA) U16.C8(VSS1) U16.D3(USB0_VSSA_TERM) U16.D4(VSS2) U16.D5(VSS3) U16.F2(USB0_VSSA_REF) U16.G8(VSS4) U16.J3(VSS5) U16.J6(VSS6) U17.4(GND) U18.5(2Y0) U18.6(GND) U18.9(3Y0) U19.2(GND) U20.2(GND) U21.2(GND) U25.2(GND) U26.2(GND) ; also on sheet 8 9
VCC_2V0: C12.1 JP1.3 TP13.1(Pin1) U4.2(VOUT)
VCC_3V3: C7.1 C22.1 C27.1 C28.1 D4.2(ANODE) JP1.1 R20.1 R37.1 R152.1 R153.1 R158.1 TP12.1(Pin1) U3.4(OUT) U3.5(SNS) U11.1(VCCA) U11.2(DIR1) U12.14(VDD)
VCC_3V3_2V0: C8.1 C24.1 C29.1 C58.1 C59.1 C84.1 C442.1 C444.1 D9.A J10.11 JP1.2 JP8.1 JS1.1 R19.1 R32.1 R33.1 R34.1 R35.1 R42.2 R43.1 R44.1 R45.1 R61.2 R62.1 R74.1 R75.1 R117.2 U11.16(VCCB) U12.1(VDDIO) U18.14(VCC) U25.1(VCCA) U26.1(VCCA) ; also on sheet 8 9
VCC_IF_LINK: C83.1 C86.1 C87.1 C89.1 C91.1 J17.1(A1) JP8.2 R116.1 R122.1 R126.1 U17.8(VCCB) U19.6(VCCB) U20.6(VCCB) U21.6(VCCB)
ACC_FC0_I2C_SCL: R77.2 U12.4(SCL/SCLK)
ACC_FC0_I2C_SDA: R84.2 U12.6(SDA/MOSI)
ACC_INT_EXP_P1_23: J9.5 R36.1 ; also on sheet 9
ARD_ADC0_0_P: J12.10 J13.3(A2) J13.8(B4) JP4.3 ; also on sheet 9
ARD_BTN_USR_P1_9: J13.2(B1) R47.2 ; also on sheet 9
ARD_CMP0_IN_A: J9.1 J11.2 J13.7(A4) ; also on sheet 9
ARD_INT_P0_15: J12.12 ; also on sheet 9
ARD_LEDB_PWM: J12.8 R161.1 ; also on sheet 9
ARD_LEDG_PWM: J12.4 R162.1 ; also on sheet 9
ARD_LEDR_PWM: J9.2 J9.13 J12.5 R164.1 ; also on sheet 9
ARD_MIK_ADC0_8_N: J7.1 J13.1(A1) JP4.1 ; also on sheet 9
ARD_MIK_FC0_I2C_SCL: J8.5 R80.2
ARD_MIK_FC0_I2C_SDA: J8.6 R88.2
ARD_MIK_FC1_USART_RXD: J8.3 J12.16 J13.4(B2) ; also on sheet 9
ARD_MIK_FC1_USART_TXD: J8.4 J12.14 J13.6(B3) ; also on sheet 9
ARD_MIK_HSSPI_MISO: J7.5 J9.12 ; also on sheet 9
ARD_MIK_HSSPI_MOSI: J7.6 J9.14 ; also on sheet 8 9
ARD_MIK_HSSPI_SCK: J7.4 J9.10 ; also on sheet 9
ARD_MIK_HSSPI_SSEL1: J7.3 J9.16 ; also on sheet 8 9
ARD_MIK_P1_5: J8.1 J12.20 ; also on sheet 9
BRG_I2C0_SCL: R91.2 U16.D6(I2C0_SCL) ; also on sheet 8
BRG_I2C0_SDA: R92.2 U16.E6(I2C0_SDA) ; also on sheet 8
BRG_INTR_ISP: U16.J5(P1_9/GPIO1[2]/U1_RTS/CTOUT_11/EMC_D2/SD_DAT0) ; also on sheet 8
BRG_INTR_ISP_DIR: U16.J7(P1_11/GPIO1[4]/U1_CTS/CTOUT_15/EMC_D4/SD_DAT2) ; also on sheet 8
BRG_ISP_CTRL: U16.A9(P2_11/GPIO1[11]/CTOUT_5/U2_RXD/EMC_A2) ; also on sheet 8
BRG_RESET_TXEN: R128.1 U16.G9(P2_6/SGPIO7/U0_DIR/EMC_A10/USB0_IND0/GPIO5[6]/CTIN_7/T3_CAP3/~{EMC_BLS1}) U21.5(DIR)
BRG_SPI1_MISO: U16.J1(P1_3/GPIO0[10]/CTOUT_8/SGPIO10/~{EMC_OE}/USB0_IND1/SSP1_MISO/SD_RST) ; also on sheet 8
BRG_SPI1_MOSI: U16.J2(P1_4/GPIO0[11]/CTOUT_9/SGPIO11/~{EMC_BLS0}/USB0_IND0/SSP1_MOSI/EMC_D15/SD_VOLT1) ; also on sheet 8
BRG_SPI1_SCLK: U16.K9(P1_19/ENET_TX_CLK/ENET_REF_CLK/SSP1_SCK/CLKOUT/I2S0_RX_MCLK/I2S1_TX_SCK) ; also on sheet 8
BRG_SPI1_SSEL: U16.K10(P1_20/GPIO0[15]/SSP1_SSEL/ENET_TXD1/T0_CAP2/SGPIO13/EMC_D11) ; also on sheet 8
BRG_TCK_SWCLK: U16.H10(P1_17/GPIO0[12]/U2_UCLK/ENET_MDIO/T0_CAP3/CAN1_TD/SGPIO11) U17.2(1A)
BRG_TDI: U16.J10(P1_18/GPIO0[13]/U2_DIR/ENET_TXD0/T0_MAT3/CAN1_RD/SGPIO12/EMC_D10) U17.3(2A)
BRG_TDO_SWO: U16.J8(P1_14/GPIO1[7]/U1_RXD/EMC_D7/T0_MAT2/SGPIO10) U19.3(A)
BRG_TMS_SWDIO: U16.K4(P1_6/GPIO1[9]/CTIN_5/~{EMC_WE}/~{EMC_BLS0}/SGPIO14/SD_CMD) U20.3(A)
BRG_TMS_SWDIO_TXEN: R124.1 U16.J4(P1_5/GPIO1[8]/CTOUT_10/~{EMC_CS0}/USB0_PWR_FAULT/SSP1_SSEL/SGPIO15/SD_POW) U20.5(DIR)
BRG_TRST_SWDRST: U16.D10(P2_5/SGPIO14/CTIN_2/USB1_VBUS/ADCTRIG1/GPIO5[5]/T3_MAT2/USB0_IND0) U21.3(A)
BRG_UART0_RXD: U16.G10(P2_0/SGPIO4/U0_TXD/EMC_A13/USB0_PPWR/GPIO5[0]/T3_CAP0/ENET_MDC) ; also on sheet 8
BRG_UART0_TXD: U16.G7(P2_1/SGPIO5/U0_RXD/EMC_A12/USB0_PWR_FAULT/GPIO5[1]/T3_CAP1) ; also on sheet 8
CAN_RXD: U25.3(A) ; also on sheet 9
CAN_TXD: U26.3(A) ; also on sheet 9
CANH: D3.1(CATHODE1) J19.7 JP23.2 U9.7(CANH)
CANL: D3.2(CATHODE2) J19.2 JP24.2 U9.6(CANL)
EXP_CMP0_IN_B: J11.1 J13.5(A3) ; also on sheet 9
EXP_CMP0_OUT: J9.3 J11.3 ; also on sheet 9
EXP_ISP_P1_29: J10.20 J12.11 ; also on sheet 8 9
FC0_I2C_SCL: J10.3 R74.2 R77.1 R80.1 ; also on sheet 9
FC0_I2C_SDA: J9.18 R75.2 R84.1 R88.1 ; also on sheet 9
FC0_USART_RXD: R24.2 ; also on sheet 8 9
FC0_USART_TXD: J10.18 R26.2 ; also on sheet 8 9
FC1_I2C_SCL: J12.19 J13.11(A6) J13.12(B6) ; also on sheet 8 9
FC1_I2C_SDA: J13.9(A5) J13.10(B5) ; also on sheet 8 9
FL_2V5: C4.1 C5.1 C69.1 C70.1 C71.1 C72.1 C81.1 C82.1 C85.1 C88.1 C90.1 J16.1(A1) L10.1 R91.1 R92.1 R96.1 R97.1 R98.1 R100.1 R105.1 R113.2 R151.1 TP11.1(Pin1) U1.2(VOUT) U16.B2(VDDA) U16.C5(VBAT) U16.F10(VDDIO1) U16.K5(VDDIO2) U17.1(VCCA) U19.1(VCCA) U20.1(VCCA) U21.1(VCCA) ; also on sheet 8
FL_BOOT0_LED: R105.2 R106.1 U16.K2(P1_1/GPIO0[8]/CTOUT_7/EMC_A6/SGPIO8/SSP0_MISO/EMC_D13)
FL_BOOT1: R99.2 U16.K1(P1_2/GPIO0[9]/CTOUT_6/EMC_A7/SGPIO9/SSP0_MOSI/EMC_D14)
FL_BOOT2: R100.2 U16.C6(P2_8/SGPIO15/CTOUT_0/U3_DIR/EMC_A8/GPIO5[7])
FL_BOOT3: R101.2 U16.B10(P2_9/GPIO1[10]/CTOUT_3/U3_BAUD/EMC_A0)
FL_ISP_BOOT: JP6.1 U16.C10(P2_7/GPIO0[7]/CTOUT_1/U3_UCLK/EMC_A9/T3_MAT3)
FL_JTAG_CLK_SWD_CLK: J16.4(B2) R102.1 U16.H2(TCK/SWDCLK)
FL_JTAG_TDI: J16.8(B4) U16.G3(TDI)
FL_JTAG_TDO_SWD_SWO: J16.6(B3) U16.H3(TDO/SWO)
FL_JTAG_TMS_SWD_IO: J16.2(B1) U16.C4(TMS/SWDIO)
FL_JTAG_TRST: R104.2 U16.B4(~{TRST})
FL_RST#: J16.10(B5) R98.2 U16.B6(~{RESET})
FL_USB0_DM: R1.2 U16.E2(USB0_DM)
FL_USB0_DP: R2.2 U16.E1(USB0_DP)
FL_USB0_ID: R3.2 R93.2
FL_USB_5V0: C2.1 C3.1 D1.A L1.2 R94.2 TP14.1(TP) U1.3(VIN)
IF_DETECT: D10.C J17.9(A5) R103.1 R125.1
IF_TCK_SWDCLK: D11.5(K4) J17.4(B2) JP13.2 U18.3(2Y1)
IF_TDI: D11.3(K2) J17.8(B4) JP14.1
IF_TDO_SWO: D11.4(K3) J17.6(B3) JP15.2 U18.11(4Y1)
IF_TMS_SWDIO: D11.6(K5) J17.2(B1) JP16.2 U18.7(3Y1)
IF_TRST_SWDRST: D11.1(K1) J17.10(B5) JP17.2 U18.15(1Y1)
MIK_EXP_BTN_WK: J8.2 J10.1 J12.15 R46.2 ; also on sheet 9
N4M_ISP_MODE: D12.C J9.7 J17.7(A4) ; also on sheet 8 9
N4M_RESET#: J7.2 J10.9 J10.10 R48.2 U18.16(1Z) ; also on sheet 9
N4M_SWDCLK: J9.19 J10.8 R115.1 U18.4(2Z) ; also on sheet 9
N4M_SWDIO: J9.17 J10.6 U18.8(3Z) ; also on sheet 9
N4M_SWO: J9.15 J9.20 U18.12(4Z) ; also on sheet 9
P0_7: J10.4 ; also on sheet 9
P0_8: J10.5 ; also on sheet 9
P0_19: J9.11 J12.6 ; also on sheet 9
P0_20: J9.4 J9.9 J12.9 ; also on sheet 9
P0_27: J12.17 ; also on sheet 9
P0_31: J10.2 ; also on sheet 9
P1_0: J12.7 ; also on sheet 9
P1_4: J12.18 ; also on sheet 9
P1_21: J12.13 ; also on sheet 9
P1_25: J12.3 ; also on sheet 9
SPI_FLASH_PIO0_2: J12.2 ; also on sheet 9
SPI_FLASH_PIO0_3: J12.1 ; also on sheet 9
SPI_FLASH_PIO0_4: J10.14 ; also on sheet 9
SPI_FLASH_PIO0_6: J10.16 ; also on sheet 9
SWD_SW_SEL: R119.2 U16.G5(P6_1/GPIO3[0]/~{EMC_DYCS1}/U0_UCLK/I2S0_RX_WS/T2_CAP0)
SYS_5V0: C6.1 C10.1 C11.1 C23.1 C57.1 C443.1 C445.1 D1.C J10.13 R60.1 R154.1 TP6.1(TP) U3.1(IN1) U3.3(EN) U3.6(IN2) U4.3(VIN) U9.3(VCC) U25.6(VCCB) U26.6(VCCB)
TAB: U1.4(TAB)
XTAL1: C79.1 U16.B1(XTAL1) Y1.2
XTAL2: C80.1 U16.C1(XTAL2) Y1.1
N00831: J1.6(SHELL1) J1.7(SHELL2) J1.8(SHELL3) J1.9(SHELL4) L2.1
N00949: C1.1 J1.1(VBUS) L1.1 U2.6(VBUS)
N00991: J1.2(D-) R1.1 U2.1(DM)
N01033: J1.3(D+) R2.1 U2.2(DP)
N01077: J1.4(ID) R3.1 TP5.1(TP) U2.3(USB_ID)
N10980: C73.1 C74.1 C75.1 L10.2 U16.E4(VDDREG1) U16.E5(VDDREG2) U16.F4(VDDREG3)
N11774: R103.2 U16.A10(P2_13/GPIO1[13]/CTIN_4/EMC_A4/U2_DIR)
N11936: R107.1 U16.J9(P6_2/GPIO3[1]/EMC_CKEOUT1/U0_DIR/I2S0_RX_SDA/T2_CAP1)
N11954: R94.1 U16.E3(USB0_VBUS)
N11988: R108.1 U16.F9(P6_5/GPIO3[4]/CTOUT_6/U0_RXD/~{EMC_RAS})
N12006: R93.1 U16.F1(USB0_ID)
N12034: R109.1 U16.F8(P6_9/GPIO3[5]/~{EMC_DYCS0}/T2_MAT2)
N12048: R95.1 U16.F3(USB0_RREF)
N12060: R110.1 U16.C9(P6_11/GPIO3[7]/EMC_CKEOUT0/T2_MAT3)
N12096: C76.1 C77.1 C78.1 R151.2 R152.2 U16.D1(USB0_VDDA3V3_DRIVER) U16.D2(USB0_VDDA3V3)
N12268: R96.2 U16.A6(DBGEN)
N12370: R97.2 U16.A4(WAKEUP0)
N12878: D8.A(ANODE) R106.2
N26173: J16.9(A5) R104.1
N35294: R111.1 U17.7(1B)
N35350: R112.1 U17.6(2B)
N35394: R113.1 U17.5(DIR)
N35580: D9.C JP8.3
N35730: R116.2 R118.1 U19.4(B)
N36212: R122.2 R123.1 U20.4(B)
N36294: JP7.1 R117.1 R119.1 U18.2(S)
N36440: JP7.2 R121.1
N36658: R126.2 R127.1 U21.4(B)
N37764: R120.1 U19.5(DIR)
N44150: R114.1 U18.1(1Y0)
N75462: J3.1 R20.2 R23.1
N75944: JP12.2 R28.1 U11.9(~{OE})
N76496: J3.2 R25.1
N76500: R25.2 U11.4(A2)
N76504: R23.2 U11.3(A1)
N76612: R24.1 U11.14(B1)
N76618: R26.1 U11.13(B2)
N79087: C32.1 R43.2 R46.1 SW1.1 SW1.2
N79544: C33.1 R44.2 R48.1 SW2.1 SW2.2
N80467: C34.1 R45.2 R47.1 SW3.1 SW3.2
N84474: Q4.6(DRAIN1) Q4.7(DRAIN1) R30.2
N84482: D4.3(CATHODE2) R30.1
N84508: Q4.3(DRAIN2) Q4.8(DRAIN2) R31.2
N84516: D4.4(CATHODE3) R31.1
N84524: D4.1(CATHODE1) R38.1
N84614: Q4.2(GATE1) R160.1 R161.2
N84618: Q4.5(GATE2) R162.2 R163.1
N84662: D5.A(ANODE) R37.2
N84682: Q5.6(DRAIN1) Q5.7(DRAIN1) R38.2
N84732: D5.C(CATHODE) Q5.3(DRAIN2) Q5.8(DRAIN2)
N84806: Q5.2(GATE1) R164.2 R165.1
N105040: R29.1 U9.8(STB)
N105919: J19.M1 J19.M2 L7.1
N108963: R32.2 TP10.1(TP) U12.9(INT2)
N108967: R33.2 R36.2 U12.11(INT1)
N109097: R34.2 R39.1 U12.7(SA0/MISO)
N109101: R35.2 R40.1 U12.10(SA1/~{CS})
N109113: C30.1 U12.8(CRST)
N109175: R41.1 U12.16(RST)
N109231: C31.1 U12.2(BYP)
N110947: Q5.5(GATE2) R42.1
N112208: U9.1(TXD) U26.4(B)
N112220: U9.4(RXD) U25.4(B)
N115095: C55.1 J7.7 R153.2
N115099: C56.1 J8.7 R154.2
N115914: J10.7 R62.2
N116004: J10.19 R60.2
N116129: J9.6 R61.1
N339341: JP12.1 R158.2
N346834: JP13.1 R111.2
N346895: JP14.2 R112.2
N346946: JP15.1 R118.2
N347023: JP16.1 R123.2
N347072: JP17.1 R127.2
N348380: R159.1 U25.5(DIR)
N350950: R19.2 U26.5(DIR)
N1378690: C25.1 R21.2 R27.2
N1379290: JP23.1 R21.1
N1379309: JP24.1 R27.1

Not connected (* = marked no-connect by the designer): J10 12*; J16 7(A4)*; J19 1* 4* 5* 6* 8* 9*; U2 4(NC1)* 5(NC2)*; U9 5(NC)*; U11 5(A3)* 6(A4)* 11(B4)* 12(B3)*; U12 15(NC)*; U16 A1(ADC0_1/ADC1_1)* A2(ADC0_0/ADC1_0/DAC)* A3(ADC0_3/ADC1_3)* A5(RTCX1)* A7(P3_3/SPI_SCK/SSP0_SCK/SPIFI_SCK/CGU_OUT1/I2S0_TX_MCLK/I2S1_TX_SCK)* A8(P3_0/I2S0_RX_SCK/I2S0_RX_MCLK/I2S0_TX_SCK/I2S0_TX_MCLK/SSP0_SCK)* B3(ADC0_2/ADC1_2)* B5(RTCX2)* B7(P3_5/GPIO1[15]/SPIFI_SIO2/U1_RXD/I2S0_TX_SDA/I2S1_RX_WS/LCD_VD12)* B8(P3_4/GPIO1[14]/SPIFI_SIO3/U1_TXD/I2S0_TX_WS/I2S1_RX_SDA/LCD_VD13)* B9(P2_12/GPIO1[12]/CTOUT_4/EMC_A3/U2_UCLK)* C3(RTC_ALARM)* C7(P3_6/GPIO0[6]/SPI_MISO/SSP0_SSEL/SPIFI_MISO/SSP0_MISO)* D7(P3_7/SPI_MOSI/SSP0_MISO/SPIFI_MOSI/GPIO5[10]/SSP0_MOSI)* D8(P2_3/SGPIO12/I2C1_SDA/U3_TXD/CTIN_1/GPIO5[3]/T3_MAT0/USB0_PPWR)* D9(P2_4/SGPIO13/I2C1_SCL/U3_RXD/CTIN_0/GPIO5[4]/T3_MAT1/USB0_PWR_FAULT)* E7(P3_8/SPI_SSEL/SSP0_MOSI/SPIFI_CS/GPIO5[11]/SSP0_SSEL)* E8(P2_10/GPIO0[14]/CTOUT_2/U2_TXD/EMC_A1)* E9(USB1_DP)* E10(USB1_DM)* F5(P2_2/SGPIO6/U0_UCLK/EMC_A11/USB0_IND1/GPIO5[2]/CTIN_6/T3_CAP2/~{EMC_CS1})* F6(P6_4/GPIO3[3]/CTIN_6/U0_TXD/~{EMC_CAS})* F7(P3_1/I2S0_TX_WS/I2S0_RX_WS/CAN0_RD/USB1_IND1/GPIO5[8]/LCD_VD15)* G1(P0_1/GPIO0[1]/SSP1_MOSI/ENET_COL/SGPIO1/ENET_TX_EN/I2S1_TX_SDA)* G2(P0_0/GPIO0[0]/SSP1_MISO/ENET_RXD1/SGPIO0/I2S0_TX_WS/I2S1_TX_WS)* G4(P1_7/GPIO1[0]/U1_DSR/CTOUT_13/EMC_D0/USB0_PPWR)* G6(P3_2/I2S0_TX_SDA/I2S0_RX_SDA/CAN0_TD/USB1_IND0/GPIO5[9]/LCD_VD14)* H1(P1_0/GPIO0[4]/CTIN_3/EMC_A5/SSP0_SSEL/SGPIO7/EMC_D12)* H4(PF_4/SSP1_SCK/GP_CLKIN/TRACECLK/I2S0_TX_MCLK/I2S0_RX_SCK)* H5(P1_8/GPIO1[1]/U1_DTR/CTOUT_12/EMC_D1/SD_VOLT0)* H6(P1_10/GPIO1[3]/U1_RI/CTOUT_14/EMC_D3/SD_DAT1)* H7(P6_0/I2S0_RX_MCLK/I2S0_RX_SCK)* H8(P1_13/GPIO1[6]/U1_TXD/EMC_D6/T0_CAP0/SGPIO9/SD_CD)* H9(P1_16/GPIO0[3]/U2_RXD/SGPIO3/ENET_CRS/T0_MAT0/EMC_D9/ENET_RX_DV)* K3(CLK0/EMC_CLK0/CLKOUT/SD_CLK/EMC_CLK01/SSP1_SCK/ENET_TX_CLK/ENET_REF_CLK)* K6(CLK2/EMC_CLK3/CLKOUT/SD_CLK/EMC_CLK23/I2S0_TX_MCLK/I2S1_RX_SCK)* K7(P1_12/GPIO1[5]/U1_DCD/EMC_D5/T0_CAP1/SGPIO8/SD_DAT3)* K8(P1_15/GPIO0[2]/U2_TXD/SGPIO2/ENET_RXD0/T0_MAT1/EMC_D8)*; U18 10(NC)* 13(4Y0)*

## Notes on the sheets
sheet 1
- Table of Contents
- Revisions
- 2
- Notes & Block Diagram
- Rev
- Description
- Date
- Approved
- 3
- System power
- X1
- Preliminary SCH design
- 08-JUL-2020
- Amish D.
- 4
- Peripheral
- A
- Agile Release
- 06-AUG-2020
- Amish D.
- 5
- Other interface
- A1
- Replaced D3 & Y2
- 20-AUG-2021
- Amish D.
- 6
- Link2 MCU
- 7
- Link2 SWD
- 8
- Link2 ISP
- 9
- LPC55S06
- 10
- Jumper & DNP Tables
- LPC55S06-EVK
- Niobe4-Nano
- This Color is for Silk
- This Color is for User Notes
- This Color is for CAD Notes
sheet 2
- System Block Diagram
sheet 3
- 2V5 Regulator
- Link2
- MICRO B
- 3V3 Regulator
- Selector
  2V0 || 3V3
- Max output current from
  NCP692 is 1A
- 2V0 Regulator
- Max output current from
  XC6203 is 400mA
- ~2V0
- Cin/Cout Minimum
  value 1.0uF required
- Mounting Holes
- GND TestPads
- 3.5x4.5
sheet 4
- CAN-FD
- P1_2
- P1_3
- Male
- DIR#  L: B to A, H: A to B
- support CAN FD
- DIR#  L: B to A, H: A to B
- H: standby
  L: normal
- USER LEDs
- RXD
- TXD
- GND
- DIR#  L:B to A, H:A to B
- JP12: open all the time, or will disable the UART0 completely,
  either through external or on-board USB to UART.
- ACCELEROMETER
- Power indicator
- push-pull
- push-pull
- active high
- VIHrst>1.04
  VILrst<0.68
- I2C Address 0X1E
- recommend 330K
  in order to reduce current.
sheet 5
- Mikroe Click Board
- CAD Note: PCB Edge Side
- socket board
- AN
  RST
  CS
  SCK
  MISO
  MOSI
  3V3
  GND
- PWM
  INT
  RX
  TX
  SCL
  SDA
  5V0
  GND
- 1. mikroBUS™ logo positioned above the socket
  2. Pin names corresponding to the routing of the mainboard
  3. A line that encloses the socket on all sides except the top, as shown above.
  4. A diagonal notch below the right-hand side pinout (serves as a guideline for add-on board insertion)
- LPCXpresso V3-style
  expansion connectors
- P0_25
- P0_26
- P1_1
- P1_3
- P1_2
- SCL
- P0_0
- SDA
- P0_1
- AREF
- P1_23
- GND
- P0_5
- SCK
- P0_20
- P0_31
- P0_7
- P0_24
- P0_28
- MISO
- MOSI
- P0_19
- P0_21
- P0_12
- P0_8
- CS
- P0_10
- P0_11
- IOREF
- PWM
- P0_12
- RESET
- RESET
- INT
- P0_11
- 3V3
- P0_4
- 5V0
- P0_30
- P0_6
- GND
- GND
- P1_29
- VIN
- PWM
- P0_3
- PWM
- P1_25
- PWM
- P0_21
- P1_9
- A0
- PWM
- PWM
- P0_20
- P1_0
- P1_10
- A1
- INT
- P1_29
- P1_11
- A2
- TXD
- P1_21
- P0_23
- A3
- RXD
- P0_28
- P0_13
- A4
- P0_27
- P0_14
- A5
- P0_14
- P0_14
- P0_0
- P0_13
- P1_4
- P1_5
- P0_9
- P1_10
- P0_23
- P1_11
- P0_16
- P0_15
- P0_23
- P0_22
- P0_18
- P0_19
- P0_2
sheet 6
- LINK2 MCU
- TRACE_D0
- TRACE_D1
- CUR_MEAS_SEL
- TRACE_CLK
- TRACE_D2
- TRACE_D3
- PU
- PU
- PU
- F
- Link2
  LPC4322 Boot Mode
  DFU USB0 = B3:0 = 0101
- PU
- F
- PU
- PU
- ISP_CTRL
- short 1-2 to force DFU mode
sheet 7
- DIR#  L: B to A, H: A to B
- S#  L:Z-Y0, H:Z-Y1
- default open, connect to on board target
- Link2 probe connected to:
- On-board Target
  Off-board Target
- Open (default)
  Shorted
- DIR#  L: B to A, H: A to B
- SWD CONN
- 3.3V or 2.0V
- DIR#  L: B to A, H: A to B
- Buffer Power Select:
- On-board Target
  Off-board Target
- 1 - 2 (default)
  2 - 3
- DIR#  L: B to A, H: A to B
